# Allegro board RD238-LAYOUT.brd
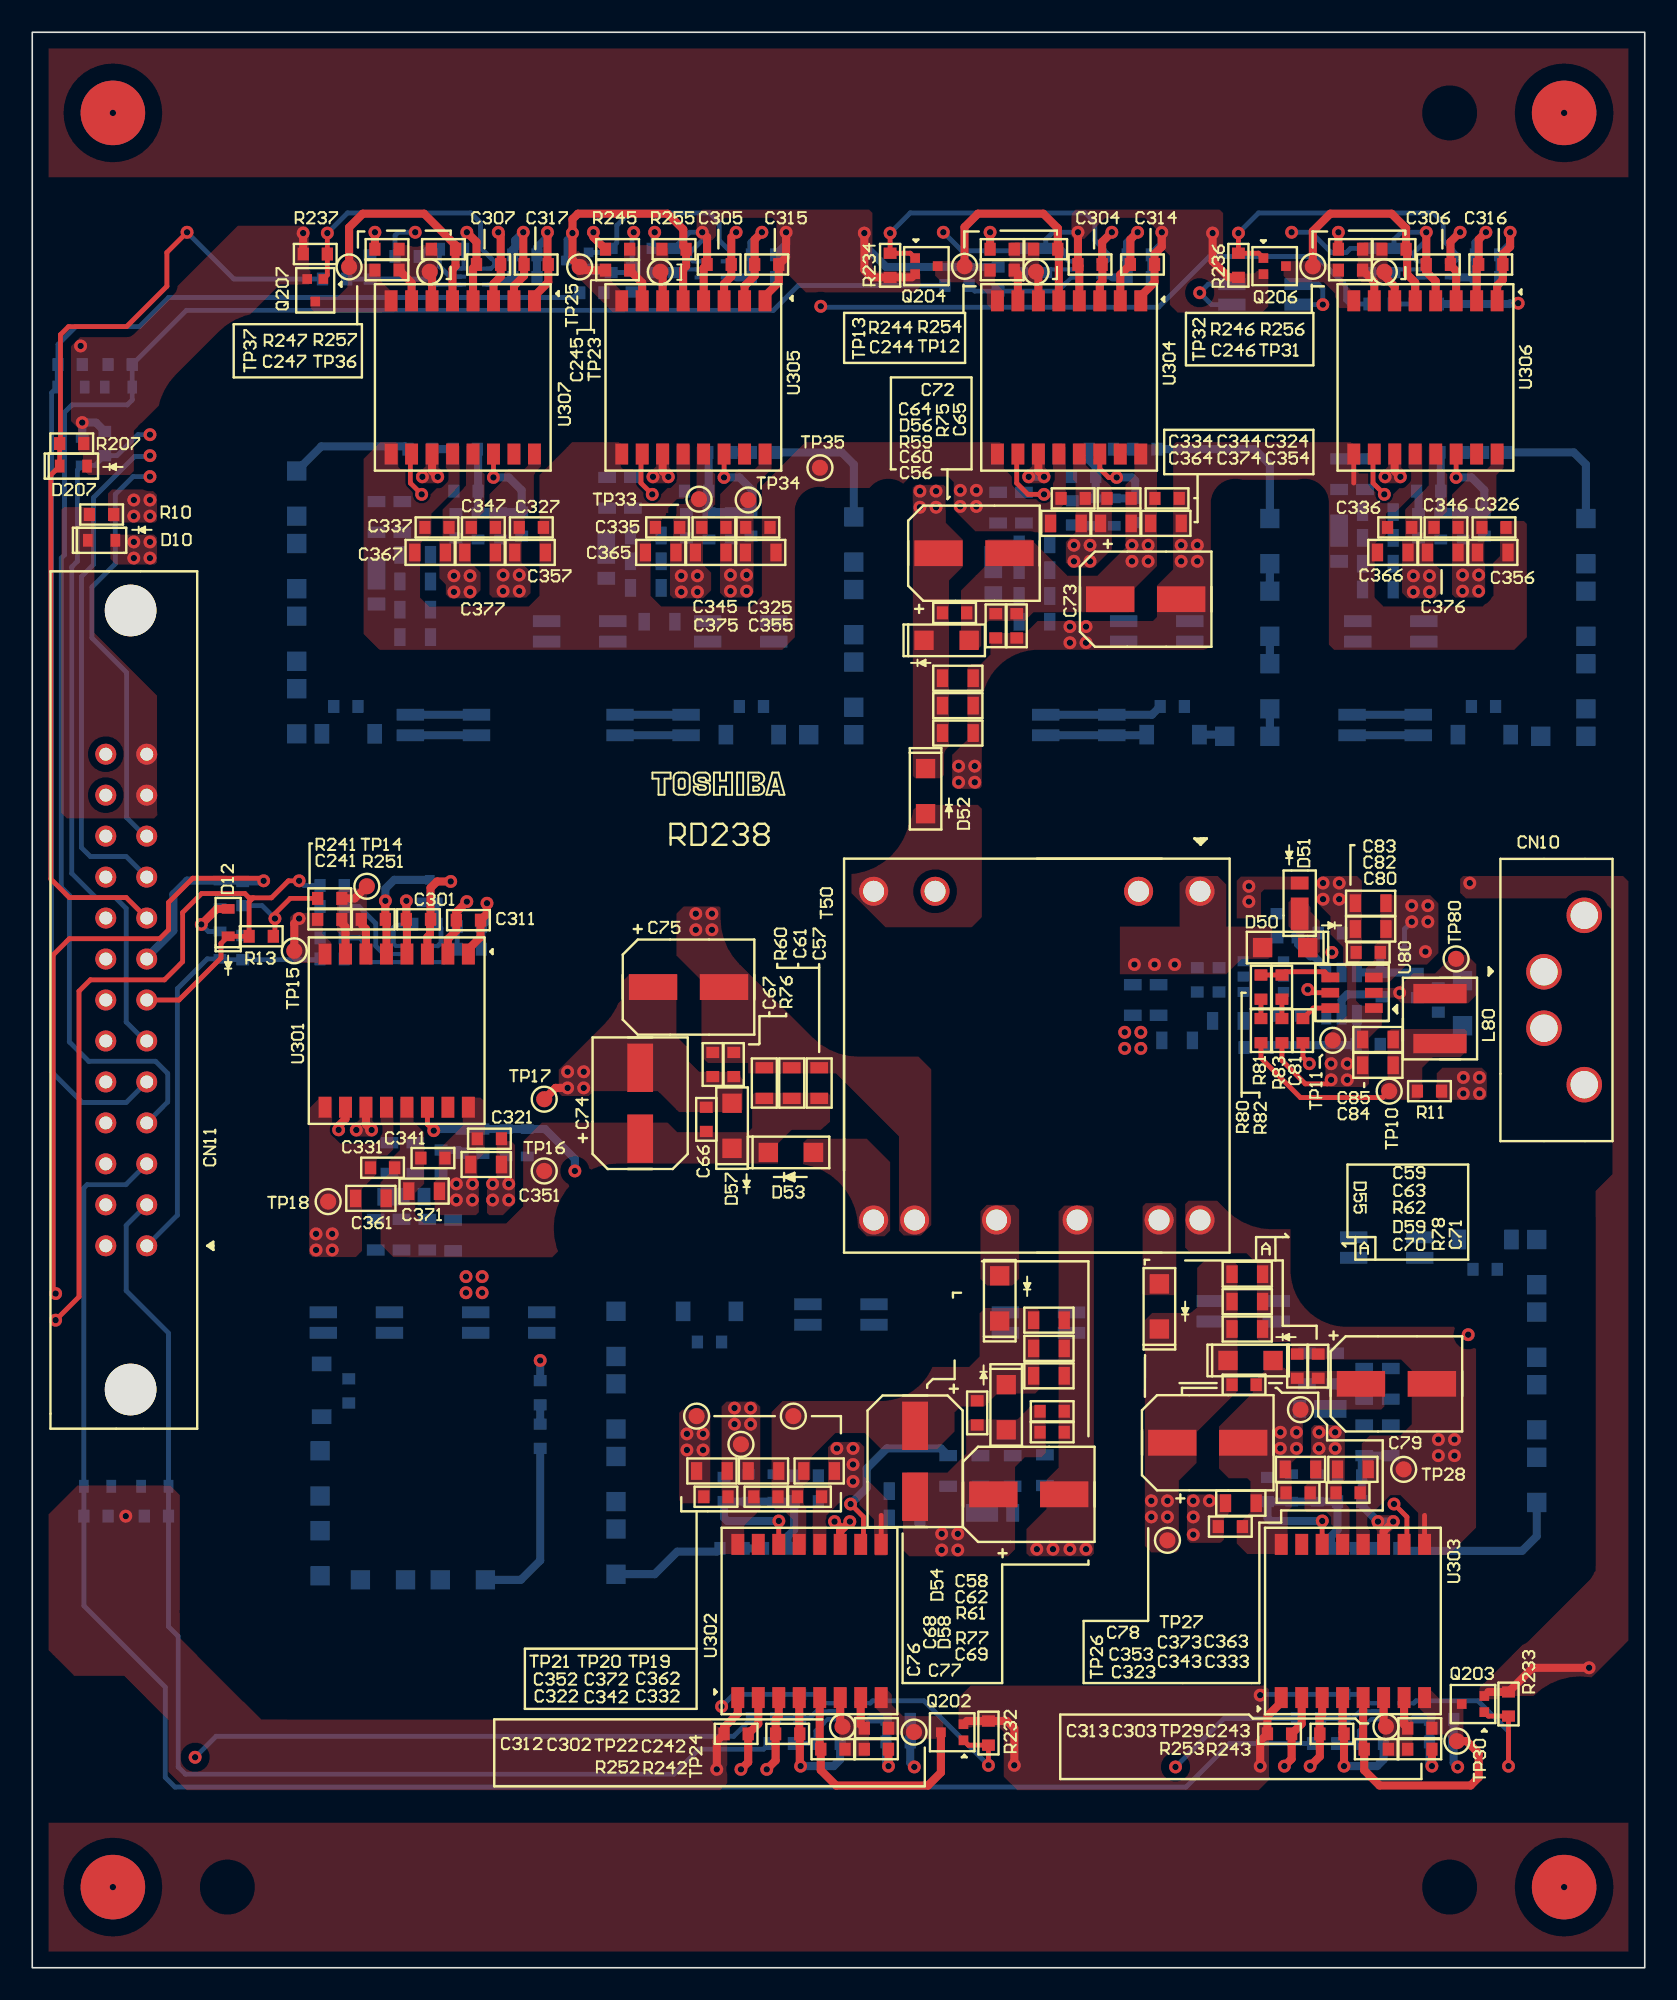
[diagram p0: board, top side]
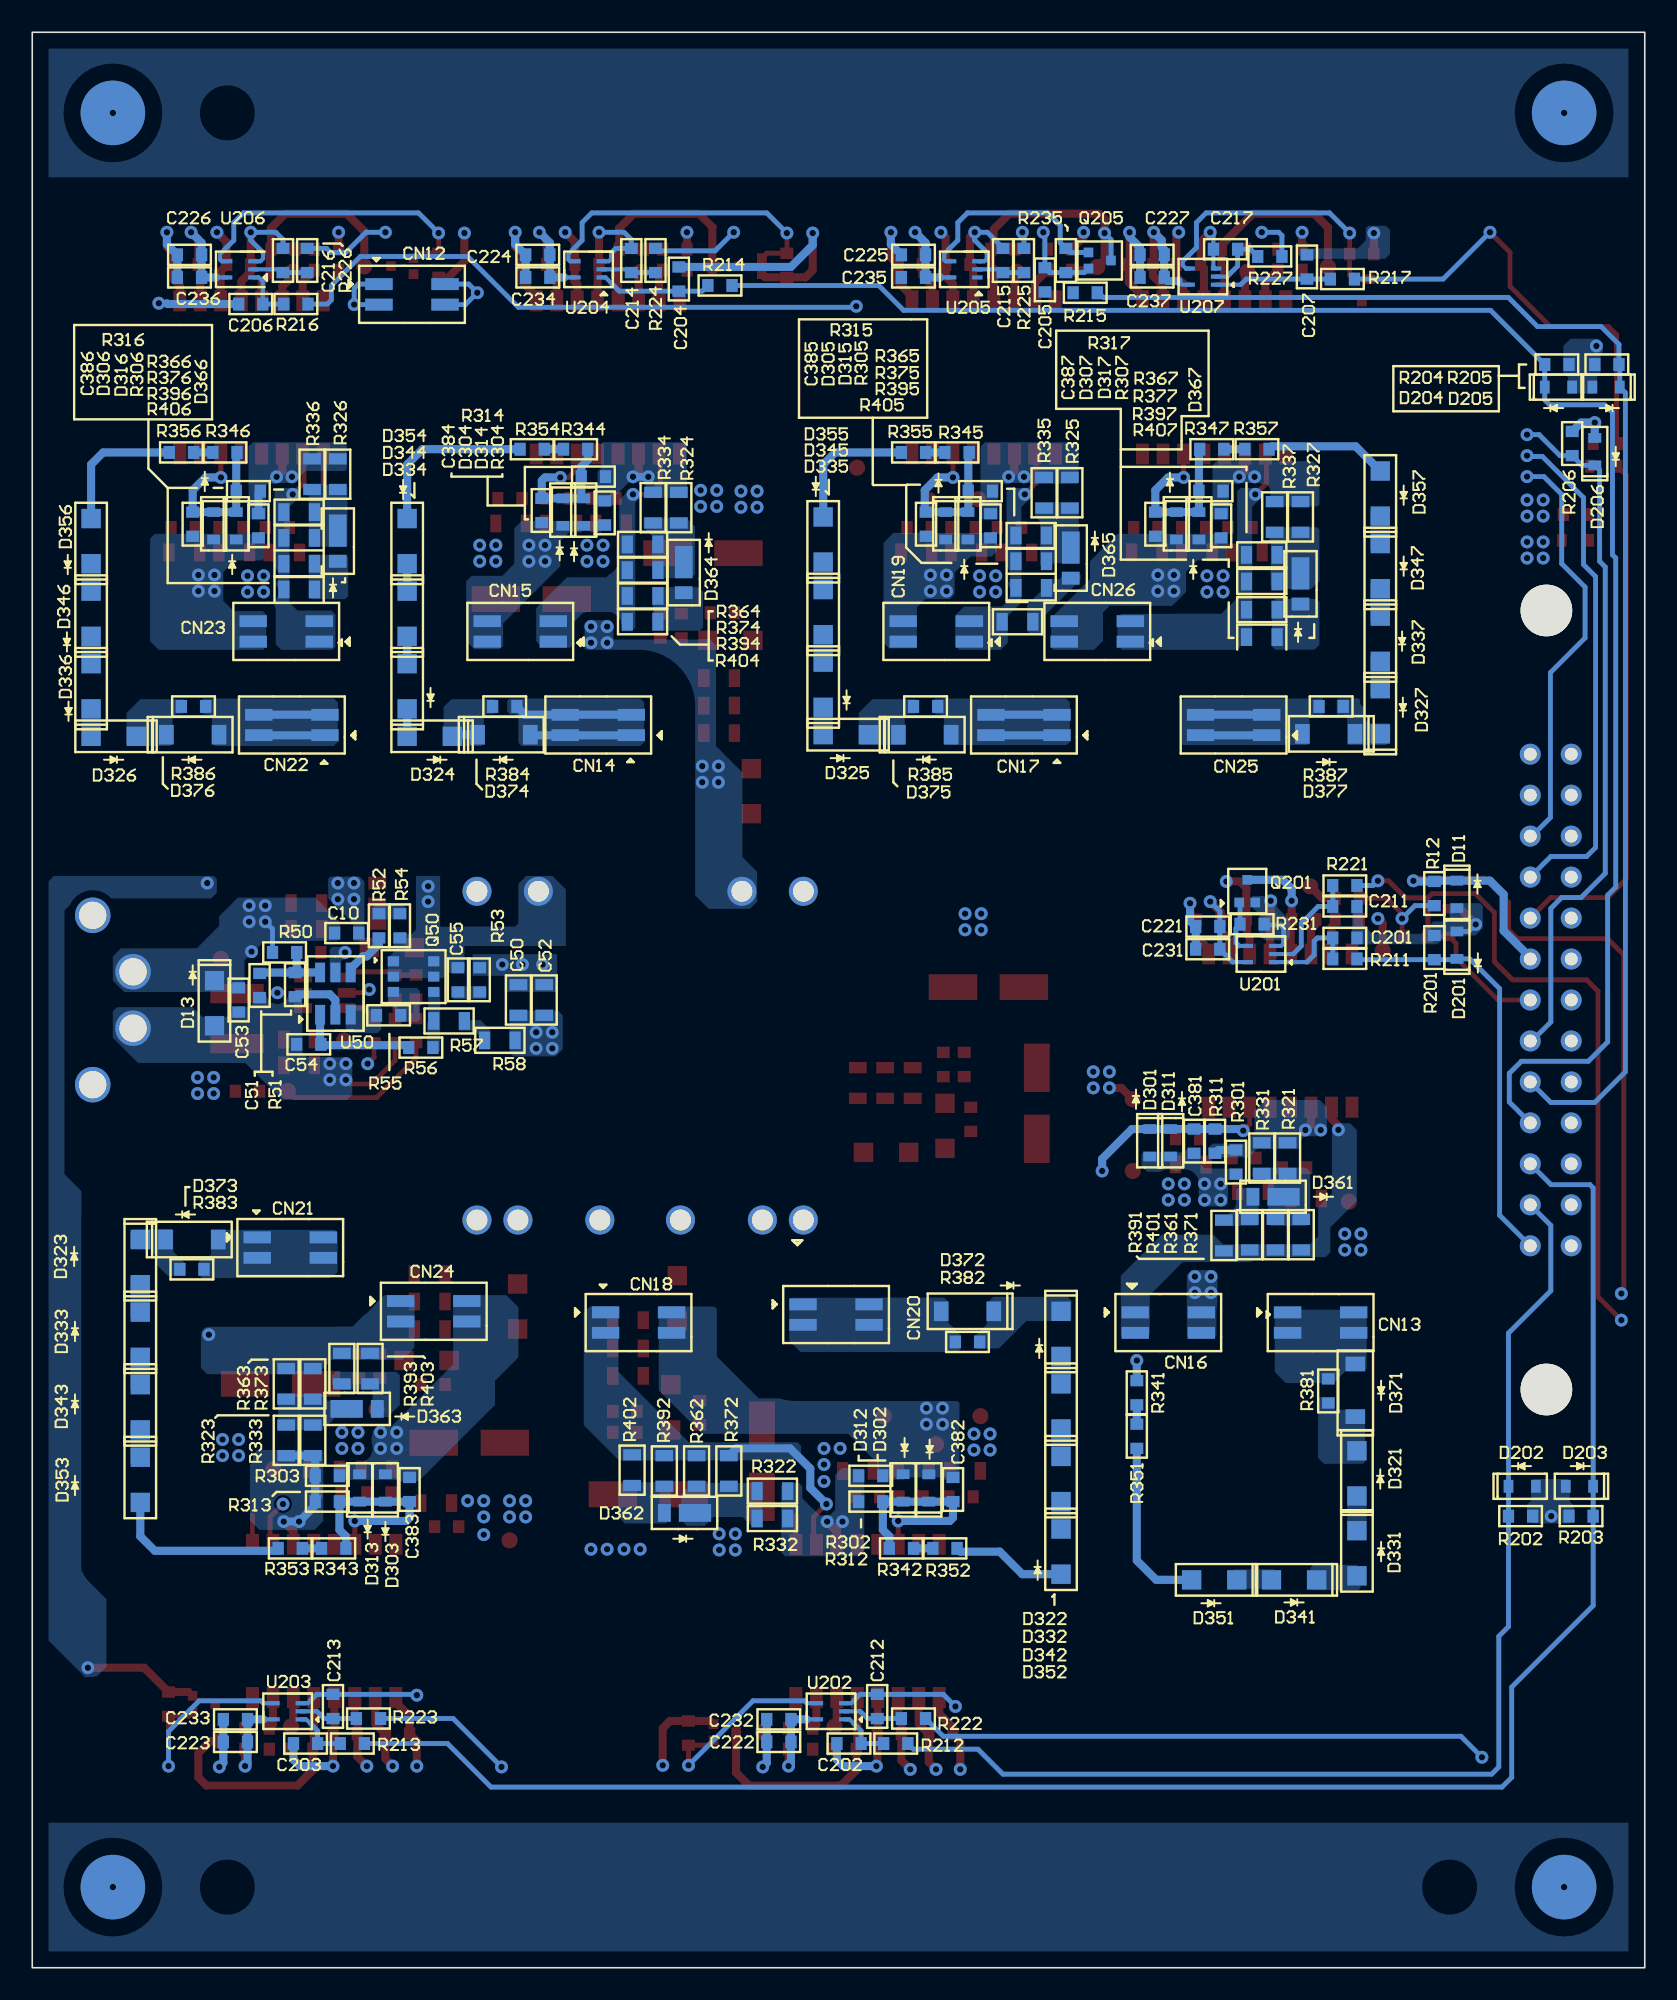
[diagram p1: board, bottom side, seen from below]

Outline 100 x 120 mm; copper layers: TOP, CONDUCTIVE2, CONDUCTIVE3, BOTTOM. Coordinates in mm from the lower left corner of the outline.
Outline path: rectangle 0,0 100,120

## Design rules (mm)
constraint set DEFAULT: 

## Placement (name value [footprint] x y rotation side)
C10  -  [1608]  80.5 64.15 0 bottom
C50  -  [2012]  69.85 60 90 bottom
C51  -  [1608]  85.9 60.9 90 bottom
C52  -  [2012]  68.25 60 90 bottom
C53  -  [1608]  87.2 60 90 bottom
C54  -  [1608]  82.85 57.25 180 bottom
C55  -  [1608]  73.6 61.25 270 bottom
C56  -  [2012]  57.4 76.55 180 top
C57  -  [2012]  48.8 54.85 270 top
C58  -  [2012]  63.05 40.15 180 top
C59  -  [2012]  75.35 43 180 top
C60  -  [2012]  57.4 78.25 180 top
C61  -  [2012]  47.1 54.85 270 top
C62  -  [2012]  63.05 38.4 180 top
C63  -  [2012]  75.35 41.3 180 top
C64  -  [1608]  57.2 84 180 top
C65  -  [1608]  61.05 83.2 90 top
C66  -  [1608]  41.8 52.6 270 top
C67  -  [1608]  42.2 56 270 top
C68  -  [1608]  58.6 34.4 90 top
C69  -  [1608]  63.25 33.2 180 top
C70  -  [1608]  75.15 36.15 180 top
C71  -  [1608]  79.75 37.3 270 top
C72  -  [SMD]  58.4 87.7 0 top
C73  -  [SMD]  69.05 84.85 0 top
C74  -  [SMD]  37.7 53.6 90 top
C75  -  [SMD]  40.7 60.8 0 top
C76  -  [SMD]  54.75 31.4 270 top
C77  -  [SMD]  61.8 29.35 0 top
C78  -  [SMD]  72.9 32.55 0 top
C79  -  [SMD]  84.6 36.2 0 top
C80  -  [1608]  82.85 62.95 0 top
C81  -  [1608]  78.8 58.1 90 top
C82  -  [2012]  83 64.4 0 top
C83  -  [2012]  83 66 0 top
C84  -  [2012]  83.45 55.95 0 top
C85  -  [2012]  83.45 57.55 0 top
C201  -  [1608]  18.6 63.85 0 bottom
C202  -  [1608]  49.35 13.9 180 bottom
C203  -  [1608]  83.05 13.9 180 bottom
C204  -  [1608]  59.9 104.7 270 bottom
C205  -  [1608]  37.2 104.65 270 bottom
C206  -  [1608]  86.45 103.15 180 bottom
C207  -  [1608]  20.95 105.45 270 bottom
C211  -  [1608]  18.6 65.8 0 bottom
C212  -  [1608]  47.6 16.2 270 bottom
C213  -  [1608]  81.35 16.2 270 bottom
C214  -  [1608]  62.85 105.85 270 bottom
C215  -  [1608]  39.8 105.85 270 bottom
C216  -  [1608]  84.45 105.85 270 bottom
C217  -  [1608]  26 106.55 180 bottom
C221  -  [1608]  27.1 64.55 180 bottom
C222  -  [1608]  53.7 14 180 bottom
C223  -  [1608]  87.4 14 180 bottom
C224  -  [1608]  68.65 106.2 180 bottom
C225  -  [1608]  45.35 106.2 180 bottom
C226  -  [1608]  90.25 106.2 180 bottom
C227  -  [1608]  30.55 106.2 180 bottom
C231  -  [1608]  27.1 63.15 180 bottom
C232  -  [1608]  53.7 15.4 180 bottom
C233  -  [1608]  87.4 15.4 180 bottom
C234  -  [1608]  68.65 104.8 180 bottom
C235  -  [1608]  45.35 104.8 180 bottom
C236  -  [1608]  90.25 104.8 180 bottom
C237  -  [1608]  30.55 104.8 180 bottom
C241  -  [1608]  18.45 65 0 top
C242  -  [1608]  52.35 14.85 180 top
C243  -  [1608]  86.05 14.85 180 top
C244  -  [1608]  60.15 105.25 0 top
C245  -  [1608]  36.3 105.25 0 top
C246  -  [1608]  81.75 105.25 0 top
C247  -  [1608]  22 105.25 0 top
C301  -  [1608]  23.95 65 180 top
C302  -  [1608]  46.85 14.5 0 top
C303  -  [1608]  80.6 14.5 0 top
C304  -  [1608]  65.6 105.6 180 top
C305  -  [1608]  42.6 105.6 180 top
C306  -  [1608]  87.2 105.6 180 top
C307  -  [1608]  28.3 105.6 180 top
C311  -  [1608]  27.05 64.95 0 top
C312  -  [1608]  43.65 14.5 180 top
C313  -  [1608]  77.35 14.5 180 top
C314  -  [1608]  68.85 105.6 0 top
C315  -  [1608]  45.55 105.6 0 top
C316  -  [1608]  90.45 105.6 0 top
C317  -  [1608]  31.25 105.6 0 top
C321  -  [1608]  28.35 51.4 180 top
C322  -  [1608]  42.4 29.2 0 top
C323  -  [1608]  74.3 27.35 0 top
C324  -  [1608]  70.38 91.1 180 top
C325  -  [1608]  45 89.3 180 top
C326  -  [1608]  90.65 89.3 180 top
C327  -  [1608]  30.95 89.3 180 top
C331  -  [1608]  21.73 49.6 0 top
C332  -  [1608]  48.2 29.2 180 top
C333  -  [1608]  81.6 29.45 180 top
C334  -  [1608]  64.55 91.1 0 top
C335  -  [1608]  39.4 89.3 0 top
C336  -  [1608]  84.8 89.3 0 top
C337  -  [1608]  25.1 89.3 0 top
C341  -  [1608]  24.85 50.2 0 top
C342  -  [1608]  45.5 29.2 180 top
C343  -  [1608]  78.5 29.45 180 top
C344  -  [1608]  67.4 91.1 0 top
C345  -  [1608]  42.27 89.3 0 top
C346  -  [1608]  87.67 89.3 0 top
C347  -  [1608]  27.98 89.3 0 top
C351  -  [2012]  28.15 49.8 180 top
C352  -  [2012]  42.15 30.8 0 top
C353  -  [2012]  74.95 28.8 0 top
C354  -  [2012]  70.3 89.55 180 top
C355  -  [2012]  45.17 87.75 180 top
C356  -  [2012]  90.58 87.75 180 top
C357  -  [2012]  30.88 87.75 180 top
C361  -  [2012]  21 47.7 0 top
C362  -  [2012]  48.8 30.8 180 top
C363  -  [2012]  81.9 30.9 180 top
C364  -  [2012]  64.1 89.55 0 top
C365  -  [2012]  38.98 87.75 0 top
C366  -  [2012]  84.38 87.75 0 top
C367  -  [2012]  24.68 87.75 0 top
C371  -  [2012]  24.3 48.15 0 top
C372  -  [2012]  45.35 30.8 180 top
C373  -  [2012]  78.65 30.9 180 top
C374  -  [2012]  67.2 89.55 0 top
C375  -  [2012]  42.08 87.75 0 top
C376  -  [2012]  87.47 87.75 0 top
C377  -  [2012]  27.77 87.75 0 top
C381  -  [1608]  27.95 51.25 270 bottom
C382  -  [1608]  42.9 29.65 90 bottom
C383  -  [1608]  76.6 29.65 90 bottom
C384  -  [1608]  68.4 90.35 270 bottom
C385  -  [1608]  44.57 89.5 270 bottom
C386  -  [1608]  90.05 89.5 270 bottom
C387  -  [1608]  30.35 89.5 270 bottom
CN10  -  [XW4M_02D1_V1DS]  93.75 60 90 top
CN11  -  [XG4A_2632]  7.1 44.76 90 top
CN12  -  [62300421021]  76.45 103.75 270 bottom
CN13  -  [62300421021]  20.1 40 270 bottom
CN14  -  [62300421021]  64.9 77.05 90 bottom
CN15  -  [62300421021]  69.73 82.85 90 bottom
CN16  -  [62300421021]  29.55 40 270 bottom
CN17  -  [62300421021]  38.5 77.05 90 bottom
CN18  -  [62300421021]  62.4 40 270 bottom
CN19  -  [62300421021]  43.94 82.85 90 bottom
CN20  -  [62300421021]  50.15 40.5 270 bottom
CN21  -  [62300421021]  84 44.65 270 bottom
CN22  -  [62300421021]  83.9 77.05 90 bottom
CN23  -  [62300421021]  84.25 82.85 90 bottom
CN24  -  [62300421021]  75.1 40.7 270 bottom
CN25  -  [62300421021]  25.5 77.05 90 bottom
CN26  -  [62300421021]  33.95 82.85 90 bottom
D10  -  [ESC]  4.3 88.5 0 top
D11  -  [ESC]  11.65 66.55 270 bottom
D12  -  [ESC]  12.15 64.8 90 top
D13  -  [S_FLAT]  88.7 59.8 90 bottom
D50  -  [S_FLAT]  77.7 63.25 0 top
D51  -  [SOD_323HE]  78.6 66 90 top
D52  -  [S_FLAT]  55.4 72.95 90 top
D53  -  [S_FLAT]  47.05 50.55 180 top
D54  -  [S_FLAT]  60 41.5 270 top
D55  -  [S_FLAT]  69.9 41 270 top
D56  -  [S_FLAT]  56.7 82.3 180 top
D57  -  [S_FLAT]  43.4 52.2 270 top
D58  -  [S_FLAT]  60.4 34.75 90 top
D59  -  [S_FLAT]  75.55 37.65 180 top
D201  -  [ESC]  11.65 63.4 90 bottom
D202  -  [ESC]  7.6 29.85 180 bottom
D203  -  [ESC]  4.05 29.85 0 bottom
D204  -  [ESC]  5.35 98 180 bottom
D205  -  [ESC]  2.4 98 0 bottom
D206  -  [ESC]  3.1 94 90 bottom
D207  -  [ESC]  2.55 93.1 0 top
D301  -  [ESC]  30.7 51.15 270 bottom
D302  -  [ESC]  44.4 29.75 90 bottom
D303  -  [ESC]  78.1 29.75 90 bottom
D304  -  [ESC]  67.1 90.25 270 bottom
D305  -  [ESC]  43.35 89.4 270 bottom
D306  -  [ESC]  88.75 89.4 270 bottom
D307  -  [ESC]  29.05 89.4 270 bottom
D311  -  [ESC]  29.4 51.15 90 bottom
D312  -  [ESC]  46 29.75 270 bottom
D313  -  [ESC]  79.7 29.75 270 bottom
D314  -  [ESC]  65.8 90.25 90 bottom
D315  -  [ESC]  41.97 89.4 90 bottom
D316  -  [ESC]  87.35 89.4 90 bottom
D317  -  [ESC]  27.65 89.4 90 bottom
D321  -  [S_FLAT]  17.85 30.65 90 bottom
D322  -  [S_FLAT]  36.2 39.3 90 bottom
D323  -  [S_FLAT]  93.3 43.75 90 bottom
D324  -  [S_FLAT]  75.35 76.35 180 bottom
D325  -  [S_FLAT]  49.55 76.45 180 bottom
D326  -  [S_FLAT]  94.95 76.35 180 bottom
D327  -  [S_FLAT]  16.4 77.9 270 bottom
D331  -  [S_FLAT]  17.85 25.7 90 bottom
D332  -  [S_FLAT]  36.2 34.8 90 bottom
D333  -  [S_FLAT]  93.3 39.25 90 bottom
D334  -  [S_FLAT]  76.75 79.45 270 bottom
D335  -  [S_FLAT]  50.95 79.55 270 bottom
D336  -  [S_FLAT]  96.35 79.45 270 bottom
D337  -  [S_FLAT]  16.4 82.4 270 bottom
D341  -  [S_FLAT]  21.75 24.05 180 bottom
D342  -  [S_FLAT]  36.2 30.3 90 bottom
D343  -  [S_FLAT]  93.3 34.75 90 bottom
D344  -  [S_FLAT]  76.75 83.95 270 bottom
D345  -  [S_FLAT]  50.95 84.05 270 bottom
D346  -  [S_FLAT]  96.35 83.95 270 bottom
D347  -  [S_FLAT]  16.4 86.9 270 bottom
D351  -  [S_FLAT]  26.7 24.05 180 bottom
D352  -  [S_FLAT]  36.2 25.8 90 bottom
D353  -  [S_FLAT]  93.3 30.25 90 bottom
D354  -  [S_FLAT]  76.75 88.45 270 bottom
D355  -  [S_FLAT]  50.95 88.55 270 bottom
D356  -  [S_FLAT]  96.35 88.45 270 bottom
D357  -  [S_FLAT]  16.4 91.4 270 bottom
D361  -  [SOD_323HE]  23.05 47.8 0 bottom
D362  -  [SOD_323HE]  59.55 28.2 0 bottom
D363  -  [SOD_323HE]  79.85 34.65 180 bottom
D364  -  [SOD_323HE]  59.6 86.5 270 bottom
D365  -  [SOD_323HE]  35.6 87.4 270 bottom
D366  -  [SOD_323HE]  81.05 88.45 270 bottom
D367  -  [SOD_323HE]  21.35 85.8 270 bottom
D371  -  [SOD_123]  17.95 35.8 90 bottom
D372  -  [SOD_123]  42 40.7 0 bottom
D373  -  [SOD_123]  90.1 45.15 180 bottom
D374  -  [SOD_123]  70.75 76.45 180 bottom
D375  -  [SOD_123]  44.65 76.45 180 bottom
D376  -  [SOD_123]  90.05 76.45 180 bottom
D377  -  [SOD_123]  19.6 76.5 0 bottom
L80  -  [4020]  87.3 58.85 270 top
NOREF  -  []  5 115 0 top
NOREF#2  -  []  95 115 0 top
NOREF#3  -  []  5 5 0 top
NOREF#4  -  []  95 5 0 top
Q50  -  [TSOP6F]  76.35 61.45 180 bottom
Q201  -  [SSM]  24.65 66.75 90 bottom
Q202  -  [SSM]  57.05 14.6 180 top
Q203  -  [SSM]  89.35 16.35 180 top
Q204  -  [SSM]  55.45 105.5 0 top
Q205  -  [SSM]  33.8 105.85 180 bottom
Q206  -  [SSM]  77.05 105.5 0 top
Q207  -  [SSM]  17.55 104 270 top
R10  -  [1608]  4.3 90.1 180 top
R11  -  [1608]  86.65 54.35 0 top
R12  -  [1608]  13.05 66.6 90 bottom
R13  -  [1608]  14.2 63.95 180 top
R50  -  [1608]  84.35 62.95 0 bottom
R51  -  [1608]  83.7 60.95 90 bottom
R52  -  [1608]  78.5 64.6 270 bottom
R53  -  [1608]  72.25 61.25 90 bottom
R54  -  [1608]  77.2 64.6 90 bottom
R55  -  [1608]  77.9 59.05 0 bottom
R56  -  [1608]  75.9 57.05 0 bottom
R57  -  [2012]  74.15 58.7 0 bottom
R58  -  [2012]  71 57.5 0 bottom
R59  -  [2012]  57.4 79.95 180 top
R60  -  [2012]  45.4 54.85 270 top
R61  -  [2012]  63.05 36.7 180 top
R62  -  [2012]  75.35 39.6 180 top
R75  -  [1608]  59.75 83.2 90 top
R76  -  [1608]  43.5 56 270 top
R77  -  [1608]  63.25 34.5 180 top
R78  -  [1608]  78.45 37.3 270 top
R80  -  [1608]  76.2 60.8 90 top
R81  -  [1608]  76.2 58.1 90 top
R82  -  [1608]  77.5 60.8 90 top
R83  -  [1608]  77.5 58.1 90 top
R201  -  [1608]  13.05 63.25 270 bottom
R202  -  [1608]  7.7 28 0 bottom
R203  -  [1608]  3.95 28 180 bottom
R204  -  [1608]  5.45 99.4 0 bottom
R205  -  [1608]  2.35 99.4 180 bottom
R206  -  [1608]  4.5 94.5 270 bottom
R207  -  [1608]  2.45 94.5 180 top
R211  -  [1608]  18.6 62.55 180 bottom
R212  -  [1608]  46.45 13.9 180 bottom
R213  -  [1608]  80.15 13.9 180 bottom
R214  -  [1608]  57.35 104.3 180 bottom
R215  -  [1608]  34.7 103.85 180 bottom
R216  -  [1608]  83.65 103.15 180 bottom
R217  -  [1608]  18.75 104.7 180 bottom
R221  -  [1608]  18.6 67.1 180 bottom
R222  -  [1608]  45.35 15.45 180 bottom
R223  -  [1608]  79.15 15.45 180 bottom
R224  -  [1608]  61.35 105.85 90 bottom
R225  -  [1608]  38.5 105.85 90 bottom
R226  -  [1608]  82.95 105.85 90 bottom
R227  -  [1608]  23.25 106.1 180 bottom
R231  -  [1608]  24.35 64.7 0 bottom
R232  -  [1608]  59.3 14.55 270 top
R233  -  [1608]  91.55 16.35 270 top
R234  -  [1608]  53.2 105.55 90 top
R235  -  [1608]  35.9 105.85 90 bottom
R236  -  [1608]  74.8 105.55 90 top
R237  -  [1608]  17.55 106.25 0 top
R241  -  [1608]  18.45 66.3 180 top
R242  -  [1608]  52.35 13.55 0 top
R243  -  [1608]  86.05 13.55 0 top
R244  -  [1608]  60.15 106.55 180 top
R245  -  [1608]  36.3 106.55 180 top
R246  -  [1608]  81.75 106.55 180 top
R247  -  [1608]  22 106.55 180 top
R251  -  [1608]  21.15 65 180 top
R252  -  [1608]  49.65 13.55 0 top
R253  -  [1608]  83.35 13.55 0 top
R254  -  [1608]  62.85 106.55 180 top
R255  -  [1608]  39.8 106.55 180 top
R256  -  [1608]  84.45 106.55 180 top
R257  -  [1608]  25.5 106.55 180 top
R301  -  [1608]  25.35 49.95 270 bottom
R302  -  [1608]  48 30.5 180 bottom
R303  -  [1608]  81.7 30.5 180 bottom
R304  -  [1608]  64.5 90.2 270 bottom
R305  -  [1608]  40.57 89.4 270 bottom
R306  -  [1608]  85.97 89.4 270 bottom
R307  -  [1608]  26.27 89.4 270 bottom
R311  -  [1608]  26.65 51.25 90 bottom
R312  -  [1608]  48 28.9 180 bottom
R313  -  [1608]  81.7 28.9 180 bottom
R314  -  [1608]  65.2 92.45 0 bottom
R315  -  [1608]  41.2 91.55 0 bottom
R316  -  [1608]  86.6 91.55 0 bottom
R317  -  [1608]  26.9 91.55 0 bottom
R321  -  [2012]  22.15 50.2 90 bottom
R322  -  [2012]  54.1 29.55 180 bottom
R323  -  [2012]  84.25 32.7 270 bottom
R324  -  [2012]  59.9 90.53 90 bottom
R325  -  [2012]  35.65 91.45 90 bottom
R326  -  [2012]  81.05 92.6 90 bottom
R327  -  [2012]  21.35 89.95 90 bottom
R331  -  [2012]  23.75 50.2 90 bottom
R332  -  [2012]  54.1 27.85 180 bottom
R333  -  [2012]  82.6 32.7 270 bottom
R334  -  [2012]  61.5 90.53 90 bottom
R335  -  [2012]  37.25 91.45 90 bottom
R336  -  [2012]  82.65 92.6 90 bottom
R337  -  [2012]  22.95 89.95 90 bottom
R341  -  [1608]  31.5 35.65 90 bottom
R342  -  [1608]  46.1 26 0 bottom
R343  -  [1608]  81.3 26 180 bottom
R344  -  [1608]  66.3 94.15 180 bottom
R345  -  [1608]  42.65 93.95 180 bottom
R346  -  [1608]  88.05 93.95 180 bottom
R347  -  [1608]  26.85 94.15 0 bottom
R351  -  [1608]  31.5 32.95 90 bottom
R352  -  [1608]  43.4 26 0 bottom
R353  -  [1608]  84 26 180 bottom
R354  -  [1608]  69 94.15 180 bottom
R355  -  [1608]  45.35 93.95 180 bottom
R356  -  [1608]  90.75 93.95 180 bottom
R357  -  [1608]  24.05 94.15 0 bottom
R361  -  [2012]  22.9 45.45 90 bottom
R362  -  [2012]  58.8 30.8 270 bottom
R363  -  [2012]  84.25 36.2 270 bottom
R364  -  [2012]  62.15 88.25 180 bottom
R365  -  [2012]  38.05 88.8 180 bottom
R366  -  [2012]  83.45 90.25 180 bottom
R367  -  [2012]  23.75 87.6 180 bottom
R371  -  [2012]  21.3 45.45 90 bottom
R372  -  [2012]  56.8 30.8 270 bottom
R373  -  [2012]  82.6 36.2 270 bottom
R374  -  [2012]  62.15 86.65 180 bottom
R375  -  [2012]  38.05 87.2 180 bottom
R376  -  [2012]  83.45 88.65 180 bottom
R377  -  [2012]  23.75 85.95 180 bottom
R381  -  [1608]  19.63 35.76 270 bottom
R382  -  [1608]  42 38.8 180 bottom
R383  -  [1608]  90.1 43.3 0 bottom
R384  -  [1608]  70.7 78.2 0 bottom
R385  -  [1608]  44.6 78.2 0 bottom
R386  -  [1608]  90 78.2 0 bottom
R387  -  [1608]  19.45 78.2 180 bottom
R391  -  [2012]  26.1 45.4 90 bottom
R392  -  [2012]  60.8 30.8 270 bottom
R393  -  [2012]  80.8 37.15 270 bottom
R394  -  [2012]  62.15 85.05 180 bottom
R395  -  [2012]  38.05 85.55 180 bottom
R396  -  [2012]  83.45 87.05 180 bottom
R397  -  [2012]  23.75 84.2 180 bottom
R401  -  [2012]  24.5 45.45 90 bottom
R402  -  [2012]  62.8 30.85 270 bottom
R403  -  [2012]  79.05 37.15 270 bottom
R404  -  [2012]  62.15 83.45 180 bottom
R405  -  [2012]  38.9 83.45 180 bottom
R406  -  [2012]  83.45 85.45 180 bottom
R407  -  [2012]  23.75 82.5 180 bottom
T50  -  [750315038]  62.3 56.55 270 top
TP10  -  [TESTPAD_C1]  84.15 54.35 270 top
TP11  -  [TESTPAD_C1]  80.65 57.5 90 top
TP12  -  [TESTPAD_C1]  62.25 105.15 90 top
TP13  -  [TESTPAD_C1]  57.82 105.49 90 top
TP14  -  [TESTPAD_C1]  20.75 67.05 90 top
TP15  -  [TESTPAD_C1]  16.25 63.05 90 top
TP16  -  [TESTPAD_C1]  31.75 49.4 90 top
TP17  -  [TESTPAD_C1]  31.75 53.85 90 top
TP18  -  [TESTPAD_C1]  18.35 47.5 90 top
TP19  -  [TESTPAD_C1]  47.2 34.2 90 top
TP20  -  [TESTPAD_C1]  43.95 32.45 90 top
TP21  -  [TESTPAD_C1]  41.2 34.2 90 top
TP22  -  [TESTPAD_C1]  50.25 14.95 270 top
TP23  -  [TESTPAD_C1]  38.95 105.15 90 top
TP24  -  [TESTPAD_C1]  54.68 14.61 270 top
TP25  -  [TESTPAD_C1]  33.95 105.45 90 top
TP26  -  [TESTPAD_C1]  70.4 26.5 90 top
TP27  -  [TESTPAD_C1]  78.65 34.6 90 top
TP28  -  [TESTPAD_C1]  85.05 30.9 90 top
TP29  -  [TESTPAD_C1]  83.95 14.95 270 top
TP30  -  [TESTPAD_C1]  88.35 14.05 270 top
TP31  -  [TESTPAD_C1]  83.85 105.15 90 top
TP32  -  [TESTPAD_C1]  79.42 105.49 90 top
TP33  -  [TESTPAD_C1]  41.35 91.05 90 top
TP34  -  [TESTPAD_C1]  44.4 91 90 top
TP35  -  [TESTPAD_C1]  48.85 93 90 top
TP36  -  [TESTPAD_C1]  24.65 105.15 90 top
TP37  -  [TESTPAD_C1]  19.65 105.45 90 top
TP80  -  [TESTPAD_C1]  88.3 62.55 0 top
U50  -  [TSOT23_6]  81.2 60.4 180 bottom
U80  -  [SOT23_6]  81.85 60.45 180 top
U201  -  [SOT_553ESV]  23.8 62.85 0 bottom
U202  -  [SOT_553ESV]  50.46 15.9 0 bottom
U203  -  [SOT_553ESV]  84.16 15.9 0 bottom
U204  -  [SOT_553ESV]  65.5 105.3 0 bottom
U205  -  [SOT_553ESV]  42.2 105.3 0 bottom
U206  -  [SOT_553ESV]  87.1 105.3 0 bottom
U207  -  [SOT_553ESV]  27.4 104.85 0 bottom
U301  -  [SO16L]  22.6 58.1 270 top
U302  -  [SO16L]  48.2 21.5 90 top
U303  -  [SO16L]  81.9 21.5 90 top
U304  -  [SO16L]  64.3 98.6 270 top
U305  -  [SO16L]  41 98.6 270 top
U306  -  [SO16L]  86.4 98.6 270 top
U307  -  [SO16L]  26.7 98.6 270 top

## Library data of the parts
C10 C53 C321-C327 C331-C337 C341-C347 = UMK107AB7105KA-T: alternate symbols: (T:1608,R241_1608,R237_1608;B:1608,R224_1608,R231_1608)
C50 C52 C56-C63 C351-C357 C361-C367 C371-C377 = GRM21BR61H106KE43L: alternate symbols: (T:2012,C56_2012,C57_2012,C82_2012;B:2012,R401_2012)
C51 C54 C80 = GCM188R71H102KA37D: alternate symbols: (T:1608,R237_1608;B:1608,R224_1608,R211_1608)
C55 C241-C247 = C0603C471K5RACTU: alternate symbols: (T:1608,R237_1608,R241_1608;B:1608,C204_1608)
C64-C71 C81 C231-C237 C311-C317 = GCM188R71H104KA57J: alternate symbols: (T:1608,R241_1608,R234_1608,R232_1608,R237_1608;B:1608,R211_1608)
C72-C79 = EMZR350ARA470ME61G: alternate symbols: (C74_SMD,C76_SMD)
C82 C83 = GRM21BZ71H475KE15K: alternate symbols: (C82_2012)
C84 C85 = GRM21BR61E226ME44K: alternate symbols: (C82_2012)
C201-C207 C211-C217 C381-C387 = C0603C101K5RACTU: alternate symbols: (T:1608;B:1608,R231_1608,R211_1608,C204_1608,R224_1608)
C221-C227 = C0603C105K3RACTU: alternate symbols: (T:1608;B:1608,R211_1608)
C301-C307 = C0603C102K3RAC: alternate symbols: (R241_1608,R237_1608)
CN10 = XW4M-02D1-V1DS
CN11 = XG4A-2632: alternate symbols: (CN11_XG4A_2632)
CN12-CN26 = 62300421021: alternate symbols: (T:62300421021;B:62300421021,CN14_62300421021)
D10-D12 D201-D207 = CEZ6V8: alternate symbols: (T:ESC,D207_ESC,D12_ESC;B:ESC,D201_ESC,D202_ESC,D203_ESC,D11_ESC)
D13 D50 = CRZ36: alternate symbols: (T:S_FLAT,D50_S_FLAT;B:S_FLAT,D13_S_FLAT)
D51 D361-D367 = CUHS10F60: alternate symbols: (T:SOD_323HE,D51_SOD_323HE;B:SOD_323HE,D364_SOD_323HE,D361_SOD_323HE,D363_SOD_323HE)
D52-D55 = CRH01: alternate symbols: (D52_S_FLAT,D53_S_FLAT,D54_S_FLAT)
D56-D59 = CRZ16: alternate symbols: (D53_S_FLAT,D54_S_FLAT,D52_S_FLAT)
D301-D307 = CUZ8V2: alternate symbols: (T:ESC;B:ESC,D11_ESC,D201_ESC)
D311-D317 = CUS05F30: alternate symbols: (T:ESC;B:ESC,D201_ESC,D11_ESC)
D321-D327 D331-D337 D341-D347 D351-D357 = CRF03A: alternate symbols: (T:S_FLAT;B:S_FLAT,D13_S_FLAT,D324_S_FLAT,D327_S_FLAT)
D371-D377 = MMSZ4678-HF: alternate symbols: (T:SOD_123;B:SOD_123,D372_SOD_123,D373_SOD_123)
L80 = 74405042047
Q50 = SSM6K819R
Q201-Q207 = SSM3K15AFS: alternate symbols: (T:SSM,Q202_SSM,Q204_SSM,Q207_SSM;B:SSM,Q201_SSM,Q205_SSM)
R10 R11 R55 R56 R351-R357 R381-R387 = RK73Z1JTTD: alternate symbols: (T:1608,R241_1608,R237_1608;B:1608,R224_1608,R231_1608,R211_1608,C204_1608)
R12 R13 R54 R201-R207 = RK73H1JTTD4701F: alternate symbols: (T:1608,R241_1608;B:1608,R224_1608,C204_1608,R231_1608,R211_1608)
R50 = RK73H1JTTD3303F: alternate symbols: (T:1608;B:1608,R231_1608)
R51 = RK73H1JTTD3302F: alternate symbols: (T:1608;B:1608,R224_1608)
R52 = RK73H1JTTD1003F: alternate symbols: (T:1608;B:1608,C204_1608)
R53 = RK73H1JTTD39R0F: alternate symbols: (T:1608;B:1608,R224_1608)
R57 R58 = UR73VD2ATTD10L0F: alternate symbols: (T:2012;B:2012,R57_2012)
R59-R62 = SG73P2ATTD2201F: alternate symbols: (C56_2012,C57_2012)
R75-R78 = RK73H1JTTD8200F: alternate symbols: (R234_1608,R232_1608,R241_1608)
R80 = RK73H1JTTD1502F: alternate symbols: (R234_1608)
R81 = RK73H1JTTD8202F: alternate symbols: (R234_1608)
R82 = RK73H1JTTD1202F: alternate symbols: (R234_1608)
R83 = RK73H1JTTD1201F: alternate symbols: (R234_1608)
R211-R217 R221-R227 = RK73H1JTTDD1000F: alternate symbols: (T:1608;B:1608,R211_1608,R224_1608)
R231-R237 = RN73R1JTTD1002F25: alternate symbols: (T:1608,R232_1608,R234_1608,R237_1608;B:1608,R231_1608,R224_1608)
R241-R247 = RK73H1JTTD3300F: alternate symbols: (R241_1608,R237_1608)
R251-R257 = RK73H1JTTD2201F: alternate symbols: (R241_1608,R237_1608)
R301-R307 = RK73H1JTTD1802F: alternate symbols: (T:1608;B:1608,C204_1608,R211_1608)
R311-R317 = RK73H1JTTD3002F: alternate symbols: (T:1608;B:1608,R224_1608,R211_1608,R231_1608)
R321-R327 R331-R337 R391-R397 R401-R407 = SG73P2ATTD10R0F: alternate symbols: (T:2012;B:2012,R401_2012,R402_2012,R404_2012)
R341-R347 = RK73H1JTTD4700F: alternate symbols: (T:1608;B:1608,R224_1608,R231_1608,R211_1608)
R361-R367 R371-R377 = SG73P2ATTD5R60F: alternate symbols: (T:2012;B:2012,R401_2012,R402_2012,R404_2012)
T50 = 750315038
TP10-TP37 TP80 = TEST_PAD
U50 = LT8306RS6#TRMPBF
U80 = LMR51430XDDCR
U201-U207 = TC7SZ08FE
U301-U307 = TLP5222: alternate symbols: (U302_SO16L)

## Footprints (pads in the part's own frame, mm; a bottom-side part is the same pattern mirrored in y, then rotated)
1608
  rect 0.7x0.8 smd: 1(-0.75,0) 2(0.75,0)
2012
  rect 0.7x1.1 smd: 1(-0.95,0) 2(0.95,0)
4020
  rect 1.2x3.3 smd: 1(-1.55,0) 2(1.55,0)
750315038
  round 1.8 hole 1.3: 1(-10.19,10.12) 2(-10.19,6.31) 5(-10.19,-6.31) 6(-10.19,-10.12) 7(10.19,-10.12) 8(10.19,-7.58) 10(10.19,-2.5) 11(10.19,2.5) 13(10.19,7.58) 14(10.19,10.12)
62300421021
  rect 0.74x1.7 smd: 1(-0.635,-2.05) 2(-0.635,2.05) 3(0.635,-2.05) 4(0.635,2.05)
ESC
  rect 0.6x0.8 smd: 1(-0.85,0) 2(0.85,0)
S_FLAT
  rect 1.2x1.2 smd: 1(-1.4,0) 2(1.4,0)
SMD
  rect 3x1.6 smd: 1(2.2,0) 2(-2.2,0)
SO16L
  rect 1.3x0.8 smd: 1(-4.75,4.445) 2(-4.75,3.175) 3(-4.75,1.905) 4(-4.75,0.635) 5(-4.75,-0.635) 6(-4.75,-1.905) 7(-4.75,-3.175) 8(-4.75,-4.445) 9(4.75,-4.445) 10(4.75,-3.175) 11(4.75,-1.905) 12(4.75,-0.635) 13(4.75,0.635) 14(4.75,1.905) 15(4.75,3.175) 16(4.75,4.445)
SOD_123
  rect 0.91x1.22 smd: 1(-1.635,0) 2(1.635,0)
SOD_323HE
  rect 0.8x1.1 smd: 1(1.25,0)
  rect 2x1.1 smd: 2(-0.65,0)
SOT23_6
  rect 1.1x0.6 smd: 1(-1.35,0.95) 2(-1.35,0) 3(-1.35,-0.95) 4(1.35,-0.95) 5(1.35,0) 6(1.35,0.95)
SOT_553ESV
  rect 0.635x0.254 smd: 1(-0.812,0.5) 2(-0.812,0) 3(-0.812,-0.5) 4(0.812,-0.5) 5(0.812,0.5)
SSM
  rect 0.6x0.6 smd: 1(-0.7,0.5) 2(-0.7,-0.5) 3(0.7,0)
TESTPAD_C1
  round 1 smd: 1(0,0)
TSOP6F
  rect 0.7x0.62 smd: 1(-1.25,0.95) 2(-1.25,0) 3(-1.25,-0.95) 4(1.25,-0.95) 5(1.25,0) 6(1.25,0.95)
TSOT23_6
  rect 0.62x1.22 smd: 1(-0.95,-1.31) 2(0,-1.31) 3(0.95,-1.31) 4(0.95,1.31) 5(0,1.31) 6(-0.95,1.31)
XG4A_2632
  round 3.2 hole 3.2 unplated: (-8.91,1) (39.39,1)
  round 1.3 hole 0.8: 1(0,0) 2(0,2.54) 3(2.54,0) 4(2.54,2.54) 5(5.08,0) 6(5.08,2.54) 7(7.62,0) 8(7.62,2.54) 9(10.16,0) 10(10.16,2.54) 11(12.7,0) 12(12.7,2.54) 13(15.24,0) 14(15.24,2.54) 15(17.78,0) 16(17.78,2.54) 17(20.32,0) 18(20.32,2.54) 19(22.86,0) 20(22.86,2.54) 21(25.4,0) 22(25.4,2.54) 23(27.94,0) 24(27.94,2.54) 25(30.48,0) 26(30.48,2.54)
XW4M_02D1_V1DS
  round 2.2 hole 1.7: 1(1.75,0) 2(-1.75,0) M1(5.25,-2.5) M2(-5.25,-2.5)

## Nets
GND: C10.1 C50.1 C51.1 C52.1 C53.1 C54.1 C80.1 C82.1 C83.1 C84.1 C85.1 C201.1 C202.1 C203.1 C204.1 C205.1 C206.1 C207.1 C211.1 C212.1 C213.1 C214.1 C215.1 C216.1 C217.1 C221.1 C222.1 C223.1 C224.1 C225.1 C226.1 C227.1 C231.1 C232.1 C233.1 C234.1 C235.1 C236.1 C237.1 C301.2 C302.2 C303.2 C304.2 C305.2 C306.2 C307.2 C311.2 C312.2 C313.2 C314.2 C315.2 C316.2 C317.2 CN10.2 CN11.2 CN11.4 CN11.6 CN11.8 CN11.10 CN11.12 CN11.14 CN11.16 CN11.18 CN11.20 CN11.22 CN11.24 CN11.26 D10.2 D11.2 D12.2 D13.1 D201.2 D202.2 D203.2 D204.2 D205.2 D206.2 D207.2 Q201.2 Q202.2 Q203.2 Q204.2 Q205.2 Q206.2 Q207.2 R51.1 R58.1 R83.1 R201.1 R202.1 R203.1 R204.1 R205.1 R206.1 R207.1 R231.1 R232.1 R233.1 R234.1 R235.1 R236.1 R237.1 TP11.1 U50.2 U80.1 U201.3 U202.3 U203.3 U204.3 U205.3 U206.3 U207.3 U301.1 U301.4 U302.1 U302.4 U303.1 U303.4 U304.1 U304.4 U305.1 U305.4 U306.1 U306.4 U307.1 U307.4
NC_LED_BOTU: U304.15
NC_LED_BOTV: U305.15
NC_LED_BOTW: U306.15
NC_LED_BR: U307.15
NC_LED_TOPU: U301.15
NC_LED_TOPV: U302.15
NC_LED_TOPW: U303.15
NETC10_2: C10.2 C50.2 C52.2 C53.2 C80.2 C82.2 C83.2 CN10.1 D13.2 D50.1 R50.2 R53.2 T50.1 U50.5 U80.3 U80.5
NETC51_2: C51.2 R50.1 R51.2 U50.6
NETC54_2: C54.2 R56.2 U50.1
NETC55_1: C55.1 D51.1 Q50.1 Q50.2 Q50.5 Q50.6 R54.1 T50.2
NETC55_2: C55.2 R53.1
NETC81_1: C81.1 L80.1 TP80.1 U80.2
NETC81_2: C81.2 U80.6
NETC84_2: C84.2 C85.2 L80.2 R11.1 R81.1 TP10.1
NETC201_2: C201.2 R211.1 U201.1
NETC202_2: C202.2 R212.1 U202.1
NETC203_2: C203.2 R213.1 U203.1
NETC204_2: C204.2 R214.1 U204.1
NETC205_2: C205.2 R215.1 U205.1
NETC206_2: C206.2 R216.1 U206.1
NETC207_2: C207.2 R217.1 U207.1
NETC211_2: C211.2 R221.1 U201.2
NETC212_2: C212.2 R222.1 U202.2
NETC213_2: C213.2 R223.1 U203.2
NETC214_2: C214.2 R224.1 U204.2
NETC215_2: C215.2 R225.1 U205.2
NETC216_2: C216.2 R226.1 U206.2
NETC217_2: C217.2 R227.1 U207.2
NETC221_2: C221.2 C222.2 C223.2 C224.2 C225.2 C226.2 C227.2 C231.2 C232.2 C233.2 C234.2 C235.2 C236.2 C237.2 C311.1 C312.1 C313.1 C314.1 C315.1 C316.1 C317.1 R10.1 R11.2 R12.1 R13.1 R241.2 R242.2 R243.2 R244.2 R245.2 R246.2 R247.2 U201.5 U202.5 U203.5 U204.5 U205.5 U206.5 U207.5 U301.2 U302.2 U303.2 U304.2 U305.2 U306.2 U307.2
NETC241_1: C241.1 Q201.3 R251.1 TP15.1 U301.5 U301.8
NETC241_2: C241.2 R241.1 R251.2 TP14.1 U301.6 U301.7
NETC242_1: C242.1 Q202.3 R252.1 TP24.1 U302.5 U302.8
NETC242_2: C242.2 R242.1 R252.2 TP22.1 U302.6 U302.7
NETC243_1: C243.1 Q203.3 R253.1 TP30.1 U303.5 U303.8
NETC243_2: C243.2 R243.1 R253.2 TP29.1 U303.6 U303.7
NETC244_1: C244.1 Q204.3 R254.1 TP13.1 U304.5 U304.8
NETC244_2: C244.2 R244.1 R254.2 TP12.1 U304.6 U304.7
NETC245_1: C245.1 Q205.3 R255.1 TP25.1 U305.5 U305.8
NETC245_2: C245.2 R245.1 R255.2 TP23.1 U305.6 U305.7
NETC246_1: C246.1 Q206.3 R256.1 TP32.1 U306.5 U306.8
NETC246_2: C246.2 R246.1 R256.2 TP31.1 U306.6 U306.7
NETC247_1: C247.1 Q207.3 R257.1 TP37.1 U307.5 U307.8
NETC247_2: C247.2 R247.1 R257.2 TP36.1 U307.6 U307.7
NETC301_1: C301.1 C302.1 C303.1 C304.1 C305.1 C306.1 C307.1 CN11.15 D11.1 R12.2 U301.3 U302.3 U303.3 U304.3 U305.3 U306.3 U307.3
NETC321_1: C57.1 C61.1 C67.1 C75.1 C321.1 C331.1 C351.1 C361.1 R60.1 R76.1 T50.8 TP18.1 U301.9 U301.12
NETC321_2: C66.1 C67.2 C74.1 C75.2 C321.2 C341.2 C351.2 C371.2 C381.2 CN16.2 CN16.4 D57.1 D301.2 D311.1 R76.2 R301.2 TP17.1 U301.16
NETC322_1: C58.1 C62.1 C69.1 C77.1 C322.1 C332.1 C352.1 C362.1 R61.1 R77.1 T50.11 TP21.1 U302.9 U302.12
NETC322_2: C68.1 C69.2 C76.1 C77.2 C322.2 C342.2 C352.2 C372.2 C382.2 CN18.2 CN18.4 D58.1 D302.2 D312.1 R77.2 R302.2 TP20.1 U302.16
NETC323_1: C59.1 C63.1 C71.1 C79.1 C323.1 C333.1 C353.1 C363.1 R62.1 R78.1 T50.14 TP28.1 U303.9 U303.12
NETC323_2: C70.1 C71.2 C78.1 C79.2 C323.2 C343.2 C353.2 C373.2 C383.2 CN24.2 CN24.4 D59.1 D303.2 D313.1 R78.2 R303.2 TP27.1 U303.16
NETC324_1: C56.1 C60.1 C65.1 C73.1 C324.1 C325.1 C326.1 C327.1 C334.1 C335.1 C336.1 C337.1 C354.1 C355.1 C356.1 C357.1 C364.1 C365.1 C366.1 C367.1 R59.1 R75.1 T50.5 TP35.1 U304.9 U304.12 U305.9 U305.12 U306.9 U306.12 U307.9 U307.12
NETC324_2: C64.1 C65.2 C72.1 C73.2 C324.2 C325.2 C326.2 C327.2 C344.2 C345.2 C346.2 C347.2 C354.2 C355.2 C356.2 C357.2 C374.2 C375.2 C376.2 C377.2 C384.2 C385.2 C386.2 C387.2 CN15.2 CN15.4 CN19.2 CN19.4 CN23.2 CN23.4 CN26.2 CN26.4 D56.1 D304.2 D305.2 D306.2 D307.2 D314.1 D315.1 D316.1 D317.1 R75.2 R304.2 R305.2 R306.2 R307.2 TP34.1 U304.16 U305.16 U306.16 U307.16
NETC331_2: C57.2 C61.2 C66.2 C74.2 C331.2 C341.1 C361.2 C371.1 D53.2 D57.2 R60.2 TP16.1 U301.13
NETC332_2: C58.2 C62.2 C68.2 C76.2 C332.2 C342.1 C362.2 C372.1 D54.2 D58.2 R61.2 TP19.1 U302.13
NETC333_2: C59.2 C63.2 C70.2 C78.2 C333.2 C343.1 C363.2 C373.1 D55.2 D59.2 R62.2 TP26.1 U303.13
NETC334_2: C56.2 C60.2 C64.2 C72.2 C334.2 C335.2 C336.2 C337.2 C344.1 C345.1 C346.1 C347.1 C364.2 C365.2 C366.2 C367.2 C374.1 C375.1 C376.1 C377.1 D52.2 D56.2 R59.2 TP33.1 U304.13 U305.13 U306.13 U307.13
NETC381_1: C381.1 D301.1 D311.2 R311.2 R341.2 U301.14
NETC382_1: C382.1 D302.1 D312.2 R312.2 R342.2 U302.14
NETC383_1: C383.1 D303.1 D313.2 R313.2 R343.2 U303.14
NETC384_1: C384.1 D304.1 D314.2 R314.2 R344.2 U304.14
NETC385_1: C385.1 D305.1 D315.2 R315.2 R345.2 U305.14
NETC386_1: C386.1 D306.1 D316.2 R316.2 R346.2 U306.14
NETC387_1: C387.1 D307.1 D317.2 R317.2 R347.2 U307.14
NETCN11_1: CN11.1 D201.1 R201.2 R211.2
NETCN11_3: CN11.3 D202.1 R202.2 R212.2
NETCN11_5: CN11.5 D203.1 R203.2 R213.2
NETCN11_7: CN11.7 D204.1 R204.2 R214.2
NETCN11_9: CN11.9 D205.1 R205.2 R215.2
NETCN11_11: CN11.11 D206.1 R206.2 R216.2
NETCN11_13: CN11.13 D12.1 R13.2 R221.2 R222.2 R223.2 R224.2 R225.2 R226.2 R227.2
NETCN11_17: CN11.17 D207.1 R207.2 R217.2
NETCN11_19: CN11.19 CN12.1 CN12.3
NETCN11_21: CN11.21 CN12.2 CN12.4
NETCN11_23: CN11.23 CN11.25 D10.1 R10.2
NETCN13_1: CN13.1 CN13.2 CN13.3 CN13.4 D371.2 R381.1
NETCN14_1: CN14.1 CN14.2 CN14.3 CN14.4 D374.2 R384.1
NETCN15_1: CN15.1 CN15.3 R364.1 R374.1 R394.1 R404.1 U304.10
NETCN16_1: CN16.1 CN16.3 R361.1 R371.1 R391.1 R401.1 U301.10
NETCN17_1: CN17.1 CN17.2 CN17.3 CN17.4 D375.2 R385.1
NETCN18_1: CN18.1 CN18.3 R362.1 R372.1 R392.1 R402.1 U302.10
NETCN19_1: CN19.1 CN19.3 R365.1 R375.1 R395.1 R405.1 U305.10
NETCN20_1: CN20.1 CN20.2 CN20.3 CN20.4 D372.2 R382.1
NETCN21_1: CN21.1 CN21.2 CN21.3 CN21.4 D373.2 R383.1
NETCN22_1: CN22.1 CN22.2 CN22.3 CN22.4 D376.2 R386.1
NETCN23_1: CN23.1 CN23.3 R366.1 R376.1 R396.1 R406.1 U306.10
NETCN24_1: CN24.1 CN24.3 R363.1 R373.1 R393.1 R403.1 U303.10
NETCN25_1: CN25.1 CN25.2 CN25.3 CN25.4 D377.2 R387.1
NETCN26_1: CN26.1 CN26.3 R367.1 R377.1 R397.1 R407.1 U307.10
NETD50_2: D50.2 D51.2
NETD52_1: D52.1 T50.6
NETD53_1: D53.1 T50.7
NETD54_1: D54.1 T50.10
NETD55_1: D55.1 T50.13
NETD321_1: D321.1 D331.2
NETD321_2: D321.2 D371.1 R381.2
NETD322_1: D322.1 D332.2
NETD322_2: D322.2 D372.1 R382.2
NETD323_1: D323.1 D333.2
NETD323_2: D323.2 D373.1 R383.2
NETD324_1: D324.1 D334.2
NETD324_2: D324.2 D374.1 R384.2
NETD325_1: D325.1 D335.2
NETD325_2: D325.2 D375.1 R385.2
NETD326_1: D326.1 D336.2
NETD326_2: D326.2 D376.1 R386.2
NETD327_1: D327.1 D337.2
NETD327_2: D327.2 D377.1 R387.2
NETD331_1: D331.1 D341.2
NETD332_1: D332.1 D342.2
NETD333_1: D333.1 D343.2
NETD334_1: D334.1 D344.2
NETD335_1: D335.1 D345.2
NETD336_1: D336.1 D346.2
NETD337_1: D337.1 D347.2
NETD341_1: D341.1 D351.2
NETD342_1: D342.1 D352.2
NETD343_1: D343.1 D353.2
NETD344_1: D344.1 D354.2
NETD345_1: D345.1 D355.2
NETD346_1: D346.1 D356.2
NETD347_1: D347.1 D357.2
NETD351_1: D351.1 R351.1
NETD352_1: D352.1 R352.1
NETD353_1: D353.1 R353.1
NETD354_1: D354.1 R354.1
NETD355_1: D355.1 R355.1
NETD356_1: D356.1 R356.1
NETD357_1: D357.1 R357.1
NETD361_1: D361.1 R391.2 R401.2
NETD361_2: D361.2 R321.1 R331.1 R361.2 R371.2
NETD362_1: D362.1 R392.2 R402.2
NETD362_2: D362.2 R322.1 R332.1 R362.2 R372.2
NETD363_1: D363.1 R393.2 R403.2
NETD363_2: D363.2 R323.1 R333.1 R363.2 R373.2
NETD364_1: D364.1 R394.2 R404.2
NETD364_2: D364.2 R324.1 R334.1 R364.2 R374.2
NETD365_1: D365.1 R395.2 R405.2
NETD365_2: D365.2 R325.1 R335.1 R365.2 R375.2
NETD366_1: D366.1 R396.2 R406.2
NETD366_2: D366.2 R326.1 R336.1 R366.2 R376.2
NETD367_1: D367.1 R397.2 R407.2
NETD367_2: D367.2 R327.1 R337.1 R367.2 R377.2
NETQ50_3: Q50.3 R55.1
NETQ50_4: Q50.4 R56.1 R57.2
NETQ201_1: Q201.1 R231.2 U201.4
NETQ202_1: Q202.1 R232.2 U202.4
NETQ203_1: Q203.1 R233.2 U203.4
NETQ204_1: Q204.1 R234.2 U204.4
NETQ205_1: Q205.1 R235.2 U205.4
NETQ206_1: Q206.1 R236.2 U206.4
NETQ207_1: Q207.1 R237.2 U207.4
NETR52_1: R52.1 R54.2
NETR52_2: R52.2 U50.4
NETR55_2: R55.2 U50.3
NETR57_1: R57.1 R58.2
NETR80_1: R80.1 R81.2
NETR80_2: R80.2 R82.2 U80.4
NETR82_1: R82.1 R83.2
NETR301_1: R301.1 R311.1 R321.2 R331.2 U301.11
NETR302_1: R302.1 R312.1 R322.2 R332.2 U302.11
NETR303_1: R303.1 R313.1 R323.2 R333.2 U303.11
NETR304_1: R304.1 R314.1 R324.2 R334.2 U304.11
NETR305_1: R305.1 R315.1 R325.2 R335.2 U305.11
NETR306_1: R306.1 R316.1 R326.2 R336.2 U306.11
NETR307_1: R307.1 R317.1 R327.2 R337.2 U307.11
NETR341_1: R341.1 R351.2
NETR342_1: R342.1 R352.2
NETR343_1: R343.1 R353.2
NETR344_1: R344.1 R354.2
NETR345_1: R345.1 R355.2
NETR346_1: R346.1 R356.2
NETR347_1: R347.1 R357.2

Pads without a net: CN10 M1 M2

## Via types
v1: diameter 0.4, hole 4, TOP to BOTTOM, 4 vias
v2: diameter 0.8, hole 0.4, TOP to BOTTOM, 261 vias

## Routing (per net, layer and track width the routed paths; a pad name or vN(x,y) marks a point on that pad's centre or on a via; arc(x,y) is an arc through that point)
GND: length 180.7
  TOP w0.3: R83.1 77.5,56.25 78.95,54.8 80.3,54.8 v2(80.55,55.05)
  TOP w0.5: U301.4 23.23,65 ; U304.1 68.75,103.64 69.6,104.5 C314.2 69.6,106.25 70.05,106.7 v2(70.05,107.6) ; U303.4 81.27,14.59 C303.2 v2(81.35,12.5) ; 57.95,15.3 R232.1 60.45,15.3 60.9,14.85 v2(60.9,12.55) ; v2(46.75,107.6) 46.75,106.05 C315.2 46.3,104.5 45.45,103.64 U305.1 ; C301.2 v2(23.2,66.15) ; 54.55,104.8 R234.1 52.05,104.8 51.6,105.25 v2(51.6,107.55) ; v2(41.55,107.6) 41.85,107.3 C305.2 41.63,105.39 U305.4 ; v2(96.55,18.6) 93.05,18.6 R233.1 90.3,17.1 ; U304.4 64.94,105.52 C304.2 v2(64.85,107.6) 64.87,107.58 ; U307.4 27.34,105.39 ; v2(47.65,12.5) 47.6,12.55 C302.2 47.56,14.54 47.56,16.75 ; U306.4 87.03,104.56 86.45,105.15 C306.2 v2(86.45,107.6) ; v2(91.65,107.6) 91.65,106.7 91.2,106.25 C316.2 91.2,104.65 90.84,104.3 U306.1 ; C307.2 27.55,107 v2(26.95,107.6) ; U303.1 77.45,16.45 76.6,15.6 C313.2 76.15,14.05 v2(76.15,12.5) ; R236.1 74.2,104.8 73.2,105.8 v2(73.2,107.55) ; v2(28.2,66) 28.2,65.35 C311.2 27.8,63.9 27.05,63.15 U301.1 ; v2(31.95,107.6) 31.95,105.65 C317.2 32,104.5 31.14,103.64 U307.1 ; v2(10.48,64.68) 11.45,65.65 D12.2 ; R237.1 v2(16.8,107.55) ; v2(42.45,12.3) 42.45,14.05 C312.2 42.9,14.9 43.76,15.75 U302.1
  BOTTOM w0.25: U201.3 22.55,63.35 22.39,63.51 ; 82.75,16.57 82.91,16.4 U203.3 ; 85.68,106.33 85.68,105.97 85.85,105.8 U206.3 ; U205.3 40.95,105.8 40.78,105.97 ; U202.3 49.21,16.4 49.05,16.57 ; 64.08,105.97 64.25,105.8 U204.3 ; v2(26.95,107.6) 26.75,107.4 C217.1 26.75,105.46 26.64,105.35 U207.3
  BOTTOM w0.3: v2(64.85,107.6) 63.3,107.6 62.85,107.15 C214.1 63.82,106.6 64.08,106.33 64.08,105.97 ; 85.68,106.33 86.45,107.1 v2(86.45,107.6) 84.9,107.6 84.45,107.15 C216.1 ; 82.75,16.57 82.36,16.95 C213.1 76.2,16.95 v2(76.15,16.9) ; D201.2 10.92,64.25 v2(10.48,64.68) ; C215.1 39.8,106.62 40.77,107.6 v2(41.55,107.6) 41.55,107.1 40.78,106.33 40.78,105.97 ; R231.1 23.55,64.65 22.57,64.65 22.39,64.47 22.39,63.51 ; 49.05,16.57 48.66,16.95 C212.1 43.5,16.95 42.85,16.3 ; v2(37.3,107.6) 37.2,107.5 C205.1 36.9,105.1 R235.1 34.75,105.1 Q205.2
  BOTTOM w0.5: D206.2 v2(3.1,95.8) 3.95,95.8 R206.1 ; C237.1 C227.1 31.3,106.65 31.95,107.3 v2(31.95,107.6) ; C231.1 C221.1 28.2,64.9 v2(28.2,66) ; v2(91.65,107.6) 91.65,106.85 C226.1 C236.1 ; C225.1 46.75,106.85 v2(46.75,107.6) ; C203.1 83.8,12.9 83.4,12.5 v2(81.35,12.5) ; C204.1 52.95,105.45 51.6,106.8 v2(51.6,107.55) ; R51.1 83.55,60.35 81.55,60.35 81.2,60 U50.2 ; 91.65,103.2 91.6,103.15 C206.1 ; v2(88.4,12.45) 88.15,12.7 C223.1 C233.1 ; v2(47.65,12.5) 49.7,12.5 50.1,12.9 C202.1 ; C234.1 C224.1 70.05,106.85 v2(70.05,107.6) ; v2(54.7,12.45) 54.45,12.7 C222.1 C232.1
  vias: v2(3,100.55) v2(5.8,28) v2(6.3,88.4) v2(6.3,87.4) v2(7.3,88.4) v2(7.3,87.4) v2(42.75,16.2) v2(67.75,58) v2(67.75,57) v2(68.75,58) v2(68.75,57) v2(80.05,67.25) v2(80.05,66.25) v2(80.55,56.05) v2(81.05,67.25) v2(81.05,66.25) v2(81.55,56.05) v2(81.55,55.05) v2(89.15,67.25) v2(92.15,103.2)
Net_13:
  vias: v1(5,5)
Net_14:
  vias: v1(5,115)
Net_15:
  vias: v1(95,5)
Net_16:
  vias: v1(95,115)
NETC10_2: length 13.5
  TOP w0.3: v2(79.1,60.65) 79.3,60.45 U80.5
  CONDUCTIVE2 w0.3: v2(79.1,60.65) 79.1,63.7 80.25,64.85 v2(85.55,64.85)
  BOTTOM w0.3: R50.2 85.1,64.4 v2(85.55,64.85)
  vias: v2(68.35,62.2) v2(69.6,62.2) v2(70.85,62.2) v2(80.6,62.95) v2(85.55,65.85) v2(86.4,63) v2(86.55,65.85) v2(86.55,64.85)
NETC51_2: length 4.9
  BOTTOM w0.5: U50.6 83.6,61.71 ; 83.6,61.77 83.67,61.7 R51.2 85.85,61.7 C51.2 ; 83.6,61.85 R50.1
NETC54_2: length 7.4
  BOTTOM w0.5: U50.1 82.15,57.3 C54.2 82.05,57.2 76.8,57.2 R56.2
NETC55_1:
  vias: v2(75.45,67.05) v2(75.45,66.1)
NETC81_1: length 9.3
  TOP w0.3: C81.1 78.8,56.45 v2(79.2,56.05)
  CONDUCTIVE3 w0.3: v2(84.8,60.45) 81.5,57.15 79.6,57.15 79.2,56.75 v2(79.2,56.05)
NETC81_2: length 2
  TOP w0.3: C81.2 79.45,59.5 U80.6
NETC84_2: length 10.1
  TOP w0.3: R81.1 76.2,56.4 78.65,53.95 83.75,53.95 TP10.1
NETC201_2: length 6.1
  BOTTOM w0.25: U201.1 20.95,62.35
  BOTTOM w0.3: 20.95,62.35 20.5,62.8 20.5,63.65 20.3,63.85 C201.2 R211.1
NETC202_2: length 3.5
  BOTTOM w0.25: 49.06,15.15 49.31,15.4 U202.1
  BOTTOM w0.3: R212.1 C202.2 48.6,14.69 49.06,15.15
NETC203_2: length 3.5
  BOTTOM w0.25: U203.1 83.01,15.4 82.76,15.15
  BOTTOM w0.3: 82.76,15.15 82.3,14.69 C203.2 R213.1
NETC204_2: length 7.1
  BOTTOM w0.25: 64.1,104.45 64.45,104.8 U204.1
  BOTTOM w0.3: R214.1 58.45,103.95 C204.2 63.6,103.95 64.1,104.45
NETC206_2: length 3.4
  BOTTOM w0.25: C206.2 85.7,104.55 85.95,104.8 U206.1
  BOTTOM w0.3: R216.1 C206.2
NETC207_2: length 7.2
  BOTTOM w0.25: 25.05,104.35 U207.1
  BOTTOM w0.3: R217.1 C207.2 24.7,104.7 25.05,104.35
NETC211_2: length 7
  BOTTOM w0.25: 21.8,62.85 U201.2
  BOTTOM w0.3: R221.1 C211.2 20.25,65.8 21.3,64.75 21.3,63.35 21.8,62.85
NETC212_2: length 3.7
  BOTTOM w0.25: 48.65,15.9 U202.2
  BOTTOM w0.3: 48.65,15.9 48.2,15.45 C212.2 R222.1
NETC213_2: length 3.6
  BOTTOM w0.25: 82.35,15.9 U203.2
  BOTTOM w0.3: 82.35,15.9 81.9,15.45 C213.2 R223.1
NETC214_2: length 3.4
  BOTTOM w0.25: U204.2 63.05,105.3 C214.2
  BOTTOM w0.3: R224.1 C214.2
NETC215_2: length 3
  BOTTOM w0.25: C215.2 40,105.3 U205.2
  BOTTOM w0.3: R225.1 C215.2
NETC216_2: length 3.4
  BOTTOM w0.25: C216.2 84.65,105.3 U206.2
  BOTTOM w0.3: R226.1 C216.2
NETC217_2: length 4.1
  BOTTOM w0.25: 25.9,104.85 U207.2
  BOTTOM w0.3: R227.1 24.45,106.55 C217.2 25.25,105.5 25.9,104.85
NETC221_2: length 78.3
  TOP w0.3: R13.1 15.05,64.05 v2(15.05,65.05) 15.05,65.35 16,66.3 R241.2
  TOP w0.5: U307.2 29.88,104.28 30.5,104.9 C317.1 30.45,105.65 v2(30.45,107.6) ; 45.02,16.75 45.02,15.12 C312.1 44.4,12.75 v2(43.95,12.3) ; U305.2 44.17,104.28 44.8,104.9 C315.1 44.8,107.15 v2(45.25,107.6) ; U306.2 89.58,105.47 C316.1 89.7,107.15 v2(90.15,107.6) ; U301.2 25.77,63.77 26.3,64.3 C311.1 26.3,65.45 v2(26.95,66.1) ; v2(86.8,12.5) R243.2 ; U304.2 67.47,104.97 C314.1 68.1,107.15 v2(68.55,107.6) ; 78.72,16.75 78.72,15.12 C313.1 78.1,12.95 v2(77.65,12.5) ; R244.2 v2(59.4,107.6) ; v2(53.1,12.5) R242.2 ; R247.2 v2(21.25,107.6) ; v2(34.8,107.6) 34.8,107.3 R245.2 ; R246.2 v2(81,107.6)
  BOTTOM w0.25: U201.5 25.55,62.35 ; U202.5 51.96,15.4 ; U203.5 85.66,15.4 ; U207.5 28.69,104.35 28.91,104.57 ; U205.5 43.7,104.8 ; U206.5 88.6,104.8 ; U204.5 67,104.8
  BOTTOM w0.3: R12.1 14.25,65.85 v2(15.05,65.05) ; 25.55,62.35 C231.2 C221.2 26.35,65.5 v2(26.95,66.1)
  BOTTOM w0.5: v2(90.15,107.6) 89.5,106.95 C226.2 C236.2 88.6,104.8 ; 85.66,15.4 86.56,15.4 ; 67,104.8 C234.2 C224.2 67.9,106.95 v2(68.55,107.6) ; v2(86.8,12.5) 86.65,12.65 C223.2 C233.2 ; 28.91,104.57 29.57,104.57 C237.2 C227.2 29.8,106.52 29.95,106.67 29.95,107.1 v2(30.45,107.6) ; C232.2 C222.2 52.95,12.65 v2(53.1,12.5) ; 43.7,104.8 C235.2 44.6,106.95 v2(45.25,107.6) ; 51.96,15.4 52.86,15.4
  vias: v2(6.3,91) v2(6.3,90) v2(7.3,91) v2(7.3,90) v2(88.75,55.2) v2(88.75,54.2) v2(89.75,55.2) v2(89.75,54.2)
NETC241_1: length 15
  TOP w0.5: TP15.1 16.25,64.75 v2(16.55,65.05) ; v2(21.9,66.15) R251.1 21.96,64.94 U301.5
  CONDUCTIVE3 w0.5: v2(16.55,65.05) 20.8,65.05 v2(21.9,66.15)
  BOTTOM w0.5: v2(21.9,66.15) 21.9,66.9 22.45,67.45 Q201.3
NETC241_2: length 5.8
  TOP w0.5: U301.7 19.43,64.53 19.2,64.75 ; R241.1 20,66.3 TP14.1 ; U301.6 20.7,64.41 20.45,64.65
NETC242_1: length 15.2
  TOP w0.5: U302.5 48.84,13.62 R252.1 48.9,12.25 49.85,11.3 55.55,11.3 56.35,12.1 Q202.3
NETC242_2: length 3.9
  TOP w0.5: 50.35,14.95 50.1,15.2 50.1,16.75 ; U302.7 51.38,15.07 C242.2
NETC243_1: length 15.4
  TOP w0.5: TP30.1 88.95,14.05 89.7,13.3 89.7,11.8 89.2,11.3 83.55,11.3 82.6,12.25 R253.1 82.53,13.62 U303.5
NETC243_2: length 3.9
  TOP w0.5: C243.2 85.08,15.07 U303.7 ; TP29.1 83.81,15.09 U303.6
NETC244_1: length 13.5
  TOP w0.5: U304.5 63.66,106.48 R254.1 63.6,107.85 62.7,108.75 58.65,108.75 57.82,107.92 TP13.1
NETC244_2: length 3.9
  TOP w0.5: C244.2 61.12,105.03 U304.7 ; TP12.1 62.4,105 62.4,103.35
NETC245_1: length 18.7
  TOP w0.5: C245.1 34.15,105.25 TP25.1 33.5,105.9 v2(33.5,107.55) 33.5,108.41 33.84,108.75 39.4,108.75 40.37,107.78 40.37,106.73 R255.1 40.55,105.5 40.37,105.31 U305.5
  BOTTOM w0.3: v2(33.5,107.55) 33.1,107.15 Q205.3
NETC245_2: length 4.1
  TOP w0.5: U305.7 37.83,104.47 C245.2 ; U305.6 39.09,105 TP23.1
NETC246_1: length 13.5
  TOP w0.5: U306.5 85.77,104.48 85.27,104.98 85.27,106.48 R256.1 85.2,107.85 84.3,108.75 80.5,108.75 79.42,107.67 TP32.1
NETC246_2: length 4.3
  TOP w0.5: 83.22,103.35 83.22,104.53 C246.2 ; TP31.1 83.85,104.88 84.5,104.23 U306.6
NETC247_1: length 13.7
  TOP w0.5: U307.5 26.07,105.31 26.25,105.5 R257.1 26.25,106.8 24.3,108.75 20.5,108.75 19.65,107.9 TP37.1
NETC247_2: length 4.1
  TOP w0.5: C247.2 23.52,104.47 U307.7 ; 24.8,103.35 24.8,105 TP36.1
NETC301_1: length 354.4
  TOP w0.3: v2(1.45,41.8) 1.3,41.95 1.3,62.8 2.3,63.8 7.9,63.8 8.45,64.35 8.45,66.05 9.95,67.55 14.19,67.55 v2(14.35,67.39)
  TOP w0.5: C304.1 66.35,107 v2(66.95,107.6) ; 24.67,65.04 24.67,64.07 24.5,63.91 24.5,62.85 ; C303.1 79.85,13.1 v2(79.25,12.5) ; v2(28.9,107.6) 29.05,107.45 C307.1 29.05,104.85 28.61,104.41 U307.3 ; 24.65,65.1 24.7,65.1 24.7,66.95 25.1,67.35 v2(25.95,67.35) ; 66.37,105.54 66.37,104.57 66.2,104.41 U304.3 ; v2(45.55,12.3) 46.1,12.85 C302.1 46.1,15.4 46.3,15.59 U302.3 ; U306.3 88.31,105.2 87.97,105.54 ; C306.1 87.95,107 v2(88.55,107.6) ; U303.3 80,15.7 79.83,15.53 79.83,14.56 ; 43.35,107.3 C305.1 43.35,104.85 42.91,104.41 U305.3
  CONDUCTIVE2 w0.3: v2(79.25,12.5) 77.95,11.2 46.65,11.2 v2(45.55,12.3) 44.45,11.2 9.65,11.2 8.4,12.45 8.4,15.65 1.2,22.85 1.2,38.1 2.6,39.5 2.6,40.65 v2(1.45,41.8) 1.2,42.05 1.2,100.9 2.05,101.75 5.7,101.75 8.3,104.35 8.3,108.1 8.95,108.75 27.75,108.75 v2(28.9,107.6) 30,108.7 42.55,108.7 v2(43.65,107.6) 44.75,108.7 65.85,108.7 v2(66.95,107.6) 68,108.65 87.5,108.65 v2(88.55,107.6)
  CONDUCTIVE3 w0.5: v2(25.95,67.35) 25.76,67.54 19.24,67.54 17.94,66.24 15.5,66.24 v2(14.35,67.39)
  BOTTOM w0.5: 7,62.54 8.75,64.29 8.75,66.55 9.6,67.4 D11.1 13,67.4 R12.2 14.31,67.35
NETC321_1:
  vias: v2(17.6,45.5) v2(17.6,44.5) v2(18.6,45.5) v2(18.6,44.5) v2(28.55,48.6) v2(28.55,47.6) v2(29.55,48.6) v2(29.55,47.6) v2(41.15,65.35) v2(41.15,64.35) v2(42.15,65.35) v2(42.15,64.35)
NETC321_2: length 1.7
  TOP w0.5: v2(33.2,54.55) 32.45,54.55 TP17.1
  vias: v2(26.3,48.6) v2(26.3,47.6) v2(26.9,42.85) v2(26.9,41.85) v2(27.3,48.6) v2(27.3,47.6) v2(27.9,42.85) v2(27.9,41.85) v2(33.2,55.55) v2(34.2,55.55) v2(34.2,54.55)
NETC322_1: length 1.8
  TOP w0.3: U302.9 52.65,28.05
  vias: v2(40.6,33.1) v2(40.6,32.1) v2(41.6,33.1) v2(41.6,32.1) v2(49.9,32.2) v2(50.9,32.2) v2(50.9,31.2) v2(50.9,30.15) v2(62.3,25.95) v2(63.3,25.95) v2(64.35,25.95) v2(65.35,25.95)
NETC322_2:
  vias: v2(43.55,34.7) v2(43.55,33.7) v2(44.55,34.7) v2(44.55,33.7) v2(56.4,26.9) v2(56.4,25.9) v2(57.4,26.9) v2(57.4,25.9)
NETC323_1: length 1.8
  TOP w0.3: U303.9 86.34,28.05
  vias: v2(72,28.95) v2(72,27.95) v2(72,26.85) v2(73,28.95) v2(87.2,32.75) v2(87.2,31.75) v2(88.2,32.75) v2(88.2,31.75)
NETC323_2:
  vias: v2(77.4,33.2) v2(77.4,32.2) v2(78.4,33.2) v2(78.4,32.2)
NETC324_1: length 1.8
  TOP w0.3: 81.95,92.06 U306.9
  vias: v2(57.55,91.6) v2(57.55,90.6) v2(57.45,74.5) v2(57.45,73.5) v2(58.55,91.6) v2(58.55,90.6) v2(58.45,74.5) v2(58.45,73.5) v2(64.35,83.15) v2(64.35,82.15) v2(65.35,83.15) v2(65.35,82.15) v2(71.25,88.2) v2(71.25,87.2) v2(72.25,88.2) v2(72.25,87.2)
NETC324_2:
  vias: v2(29.2,86.35) v2(29.2,85.35) v2(30.2,86.35) v2(30.2,85.35) v2(43.3,86.35) v2(43.3,85.35) v2(44.3,86.35) v2(44.3,85.35) v2(68.2,88.2) v2(68.2,87.2) v2(69.2,88.2) v2(69.2,87.2) v2(88.7,86.35) v2(88.7,85.35) v2(89.7,86.35) v2(89.7,85.35)
NETC333_2:
  vias: v2(69.4,28.95) v2(69.4,27.95) v2(70.4,28.95) v2(70.4,27.95) v2(79.8,33.2) v2(79.8,32.2) v2(80.8,33.2) v2(80.8,32.2)
NETC334_2:
  vias: v2(26.15,86.3) v2(26.15,85.3) v2(27.15,86.3) v2(27.15,85.3) v2(40.25,86.3) v2(40.25,85.3) v2(41.25,86.3) v2(41.25,85.3) v2(55.05,91.55) v2(55.05,90.55) v2(56.05,91.55) v2(56.05,90.55) v2(64.6,88.2) v2(64.6,87.2) v2(65.6,88.2) v2(65.6,87.2) v2(85.65,86.3) v2(85.65,85.3) v2(86.65,86.3) v2(86.65,85.3)
NETC381_1: length 25.8
  TOP w0.3: 24.5,53.35 24.5,52.3 v2(24.9,51.9)
  CONDUCTIVE2 w0.5: v2(31.5,37.65) 31.5,47.25 v2(33.65,49.4)
  BOTTOM w0.5: R341.2 v2(31.5,37.65) ; v2(33.65,49.4) 33.65,50.15 31.8,52 D301.1 D311.2 C381.1 R311.2 25,52 v2(24.9,51.9)
NETC382_1: length 13.4
  TOP w0.3: U302.14 46.3,27.7 v2(46.3,27.7)
  BOTTOM w0.5: R342.2 46.85,26.75 47.25,27.15 R312.2 D312.2 D302.1 C382.1 42.9,27.9 43.1,27.7 v2(46.3,27.7)
NETC383_1: length 13.4
  TOP w0.3: v2(80,27.7) 80,27.7 U303.14
  BOTTOM w0.5: v2(80,27.7) 76.8,27.7 76.6,27.9 C383.1 D303.1 D313.2 R313.2 80.95,27.15 80.55,26.75 R343.2
NETC384_1: length 10.4
  TOP w0.3: U304.14 66.2,92.94 66.75,92.4 v2(67.25,92.4)
  BOTTOM w0.5: v2(67.25,92.4) 68.2,92.4 68.4,92.2 C384.1 D304.1 D314.2 65.95,91.25 R314.2 65.95,93.07 65.55,93.47 R344.2
NETC385_1: length 11.3
  TOP w0.3: U305.14 42.91,92.41 v2(42.9,92.4)
  BOTTOM w0.5: v2(42.9,92.4) 43.86,92.4 44.65,91.61 44.65,90.25 C385.1 D305.1 D315.2 41.95,90.27 R315.2 41.95,93.9 R345.2
NETC386_1: length 11.3
  TOP w0.3: v2(88.3,92.4) 88.31,92.41 U306.14
  BOTTOM w0.5: R346.2 87.35,93.9 R316.2 D316.2 D306.1 C386.1 90.05,91.61 89.26,92.4 v2(88.3,92.4)
NETC387_1: length 11.5
  TOP w0.3: U307.14 28.61,92.41 v2(28.6,92.4)
  BOTTOM w0.5: R347.2 27.65,94.1 R317.2 D317.2 D307.1 C387.1 30.35,91.61 29.56,92.4 v2(28.6,92.4)
NETCN11_1: length 26.4
  BOTTOM w0.3: R211.2 17.8,62.5 R201.2 11.7,62.5 D201.1 10.85,62.55 9,60.7 9,46.66 CN11.1
NETCN11_3: length 74.3
  BOTTOM w0.3: CN11.3 5.83,46.02 5.83,41.98 8.45,39.35 D202.1 R202.2 8.45,21.15 9.05,20.55 9.05,12.45 9.5,12 39.8,12 41.35,13.55 45.35,13.55 R212.2
NETCN11_5: length 115.7
  BOTTOM w0.3: R213.2 74.25,13.9 71.55,11.2 8.85,11.2 8.25,11.8 8.25,17.4 3.2,22.45 R203.2 D203.1 3.2,48.35 3.4,48.55 5.81,48.55 CN11.5
NETCN11_7: length 109
  BOTTOM w0.3: CN11.7 8.4,53.68 8.4,55.45 7.65,56.2 3.5,56.2 2.3,57.4 2.3,66.5 1.8,67 1.8,87.4 2,87.6 2,96.43 2.47,96.9 5.9,96.9 6.2,97.2 D204.1 R204.2 9.56,102.76 45.96,102.76 47.5,104.3 R214.2
NETCN11_9: length 86.2
  BOTTOM w0.3: CN11.9 5.83,53.65 3.1,53.65 1.2,55.55 1.2,97.65 D205.1 1.55,99.35 R205.2 1.6,100.65 2.7,101.75 6.65,101.75 8.46,103.56 33.56,103.56 33.95,103.95
NETCN11_11: length 126.9
  CONDUCTIVE3 w0.3: v2(7.3,95.05) 7.3,97.45 12.85,103 48.89,103 v2(48.9,103.01)
  BOTTOM w0.3: v2(48.9,103.01) 48.96,102.95 69.85,102.95 73,106.1 79.65,106.1 81.45,104.3 81.45,103.4 81.7,103.15 R216.2 ; 7,57.46 5.83,58.63 5.83,65.67 5.15,66.35 3.95,66.35 2.45,67.85 2.45,86.85 2.8,87.2 2.8,92.85 D206.1 3.9,93.15 R206.2 5.25,93.75 6.55,95.05 v2(7.3,95.05)
NETCN11_13: length 350.8
  TOP w0.3: CN11.13 9.1,60 11.7,62.6 11.7,63.5 D12.1 R13.2 13.45,66.08 13.7,66.33 ; v2(16.55,67.39) 15.89,67.39 14.83,66.33 13.7,66.33 ; 13.7,66.33 13.45,66.33 13.18,66.6 10.5,66.6 9.32,65.42 9.32,62.38 8.2,61.25 3.6,61.25 2.9,60.55 2.9,41.6 v2(1.45,40.15)
  CONDUCTIVE3 w0.3: v2(70.9,12.45) 69.65,11.2 11.85,11.2 10.1,12.95 v2(10.1,13.05) 10.1,13.95 1.2,22.85 1.2,39.9 v2(1.45,40.15) 2.55,41.25 2.55,42.2 1.16,43.59 1.16,100.26 2.55,101.65 5.6,101.65 8.25,104.3 8.25,107.9 9.1,108.75 22.6,108.75 v2(23.75,107.6) 24.9,108.75 37.45,108.75 v2(38.6,107.6) 39.8,108.8 55.3,108.8 v2(56.5,107.6) 57.65,108.75 76.95,108.75 v2(78.1,107.6)
  BOTTOM w0.3: R224.2 61.2,106.45 57.65,106.45 v2(56.5,107.6) ; v2(78.1,107.6) 79.3,107.6 80.55,106.35 81.5,106.35 81.75,106.6 R226.2 ; v2(38.6,107.6) 38.5,107.5 R225.2 ; R227.2 22.5,107.4 22.7,107.6 v2(23.75,107.6) ; v2(70.9,12.45) 73.9,15.45 R223.2 ; R221.2 16.84,67.1 v2(16.55,67.39) ; R222.2 43.5,14.35 11.4,14.35 v2(10.1,13.05)
NETCN11_17: length 62.3
  TOP w0.3: CN11.17 5.83,66.35 2.3,66.35 1.15,67.5 1.15,92.55 D207.1 R207.2 1.75,94.55 1.75,101.25 2.25,101.75 5.85,101.75 8.35,104.25 8.35,106.35 v2(9.6,107.6)
  BOTTOM w0.3: v2(9.6,107.6) 12.5,104.7 R217.2
NETCN11_19: length 116.6
  CONDUCTIVE2 w0.3: v2(7.3,93.75) 7.25,93.7 6.9,93.7 6.25,94.35 6.25,96.35 12.66,102.76 47.06,102.76 48.4,104.1 49.6,104.1 50.94,102.76 79.68,102.76 v2(80.03,103.11)
  BOTTOM w0.3: CN12.1 79.77,104.39 80.03,104.11 v2(80.03,103.11) CN12.3 ; 7.3,93.7 6.35,93.7 3.8,91.15 3.8,87 3.05,86.25 3.05,69.45 3.6,68.9 5.82,68.9 CN11.19
NETCN11_21: length 106.5
  CONDUCTIVE2 w0.3: v2(7.3,92.45) 7.2,92.35 6.85,92.35 5.45,93.75 5.45,96.69 12.32,103.56 46.46,103.56 47.85,104.95 50.2,104.95 51.3,103.85 v2(72.4,103.85)
  BOTTOM w0.3: CN12.2 72.94,104.39 v2(72.4,103.85) 73.14,103.11 CN12.4 ; 7,70.16 5.85,71.31 5.85,80.3 3.7,82.45 3.7,85.6 5.15,87.05 5.15,91.35 6.25,92.45 v2(7.3,92.45)
NETCN14_1: length 13.6
  BOTTOM w0.5: CN14.3 CN14.4 69.44,77.69 R384.1 ; 62.85,76.42 69.08,76.42 D374.2
NETCN15_1: length 3.7
  TOP w0.3: U304.10 61.05,93.78 61.05,92.05 61.75,91.35 62.6,91.35
  vias: v2(62.75,91.35)
NETCN16_1: length 1.6
  TOP w0.5: v2(19,51.95) 19,52.2 19.43,52.62 U301.10
NETCN17_1: length 8.2
  BOTTOM w0.5: CN17.3 CN17.4 ; 36.45,76.42 40.55,76.42
NETCN18_1: length 11.3
  TOP w0.3: v2(50.75,28.75) 51.55,27.95 51.55,26.43 U302.10
  BOTTOM w0.5: R372.1 56.35,32.2 53,32.2 51.75,30.95 51.75,29.75 v2(50.75,28.75)
NETCN19_1: length 2.8
  TOP w0.3: v2(38.45,91.35) 37.75,92.05 37.75,93.78 U305.10
NETCN22_1: length 8.2
  BOTTOM w0.5: 81.85,76.42 85.95,76.42 ; CN22.3 CN22.4
NETCN23_1: length 2.8
  TOP w0.3: 83.22,93.85 83.15,93.78 83.15,92.05 v2(83.85,91.35)
NETCN24_1: length 15.3
  TOP w0.3: U303.10 85.25,26.43 85.25,27.95 v2(84.45,28.75)
  CONDUCTIVE3 w0.5: v2(84.45,28.75) 84.45,34.65 v2(89.05,39.25)
NETCN25_1: length 8.2
  BOTTOM w0.5: CN25.3 CN25.4 ; 23.45,76.42 27.55,76.42
NETCN26_1: length 2.8
  TOP w0.3: v2(24.15,91.35) 23.45,92.05 23.45,93.78 U307.10
NETD324_1: length 1.7
  BOTTOM w0.5: D324.1 D334.2
NETD324_2: length 1.6
  BOTTOM w0.5: D324.2 73.85,76.45 D374.1
NETD334_1: length 1.7
  BOTTOM w0.5: D334.1 D344.2
NETD344_1: length 1.7
  BOTTOM w0.5: D344.1 D354.2
NETD351_1: length 10.8
  BOTTOM w0.5: R351.1 31.5,25.25 30.3,24.05 D351.1
